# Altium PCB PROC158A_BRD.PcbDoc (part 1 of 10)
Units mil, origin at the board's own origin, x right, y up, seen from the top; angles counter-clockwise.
Board outline 3346.45 x 4921.26 mil, 8 copper layers (Top Layer, GND1, SIG1, PWR1, PWR2, SIG2, GND2, Bottom Layer), stack 54.534 mil thick; 718 components, 459 nets, 2307 pads, 1179 vias.
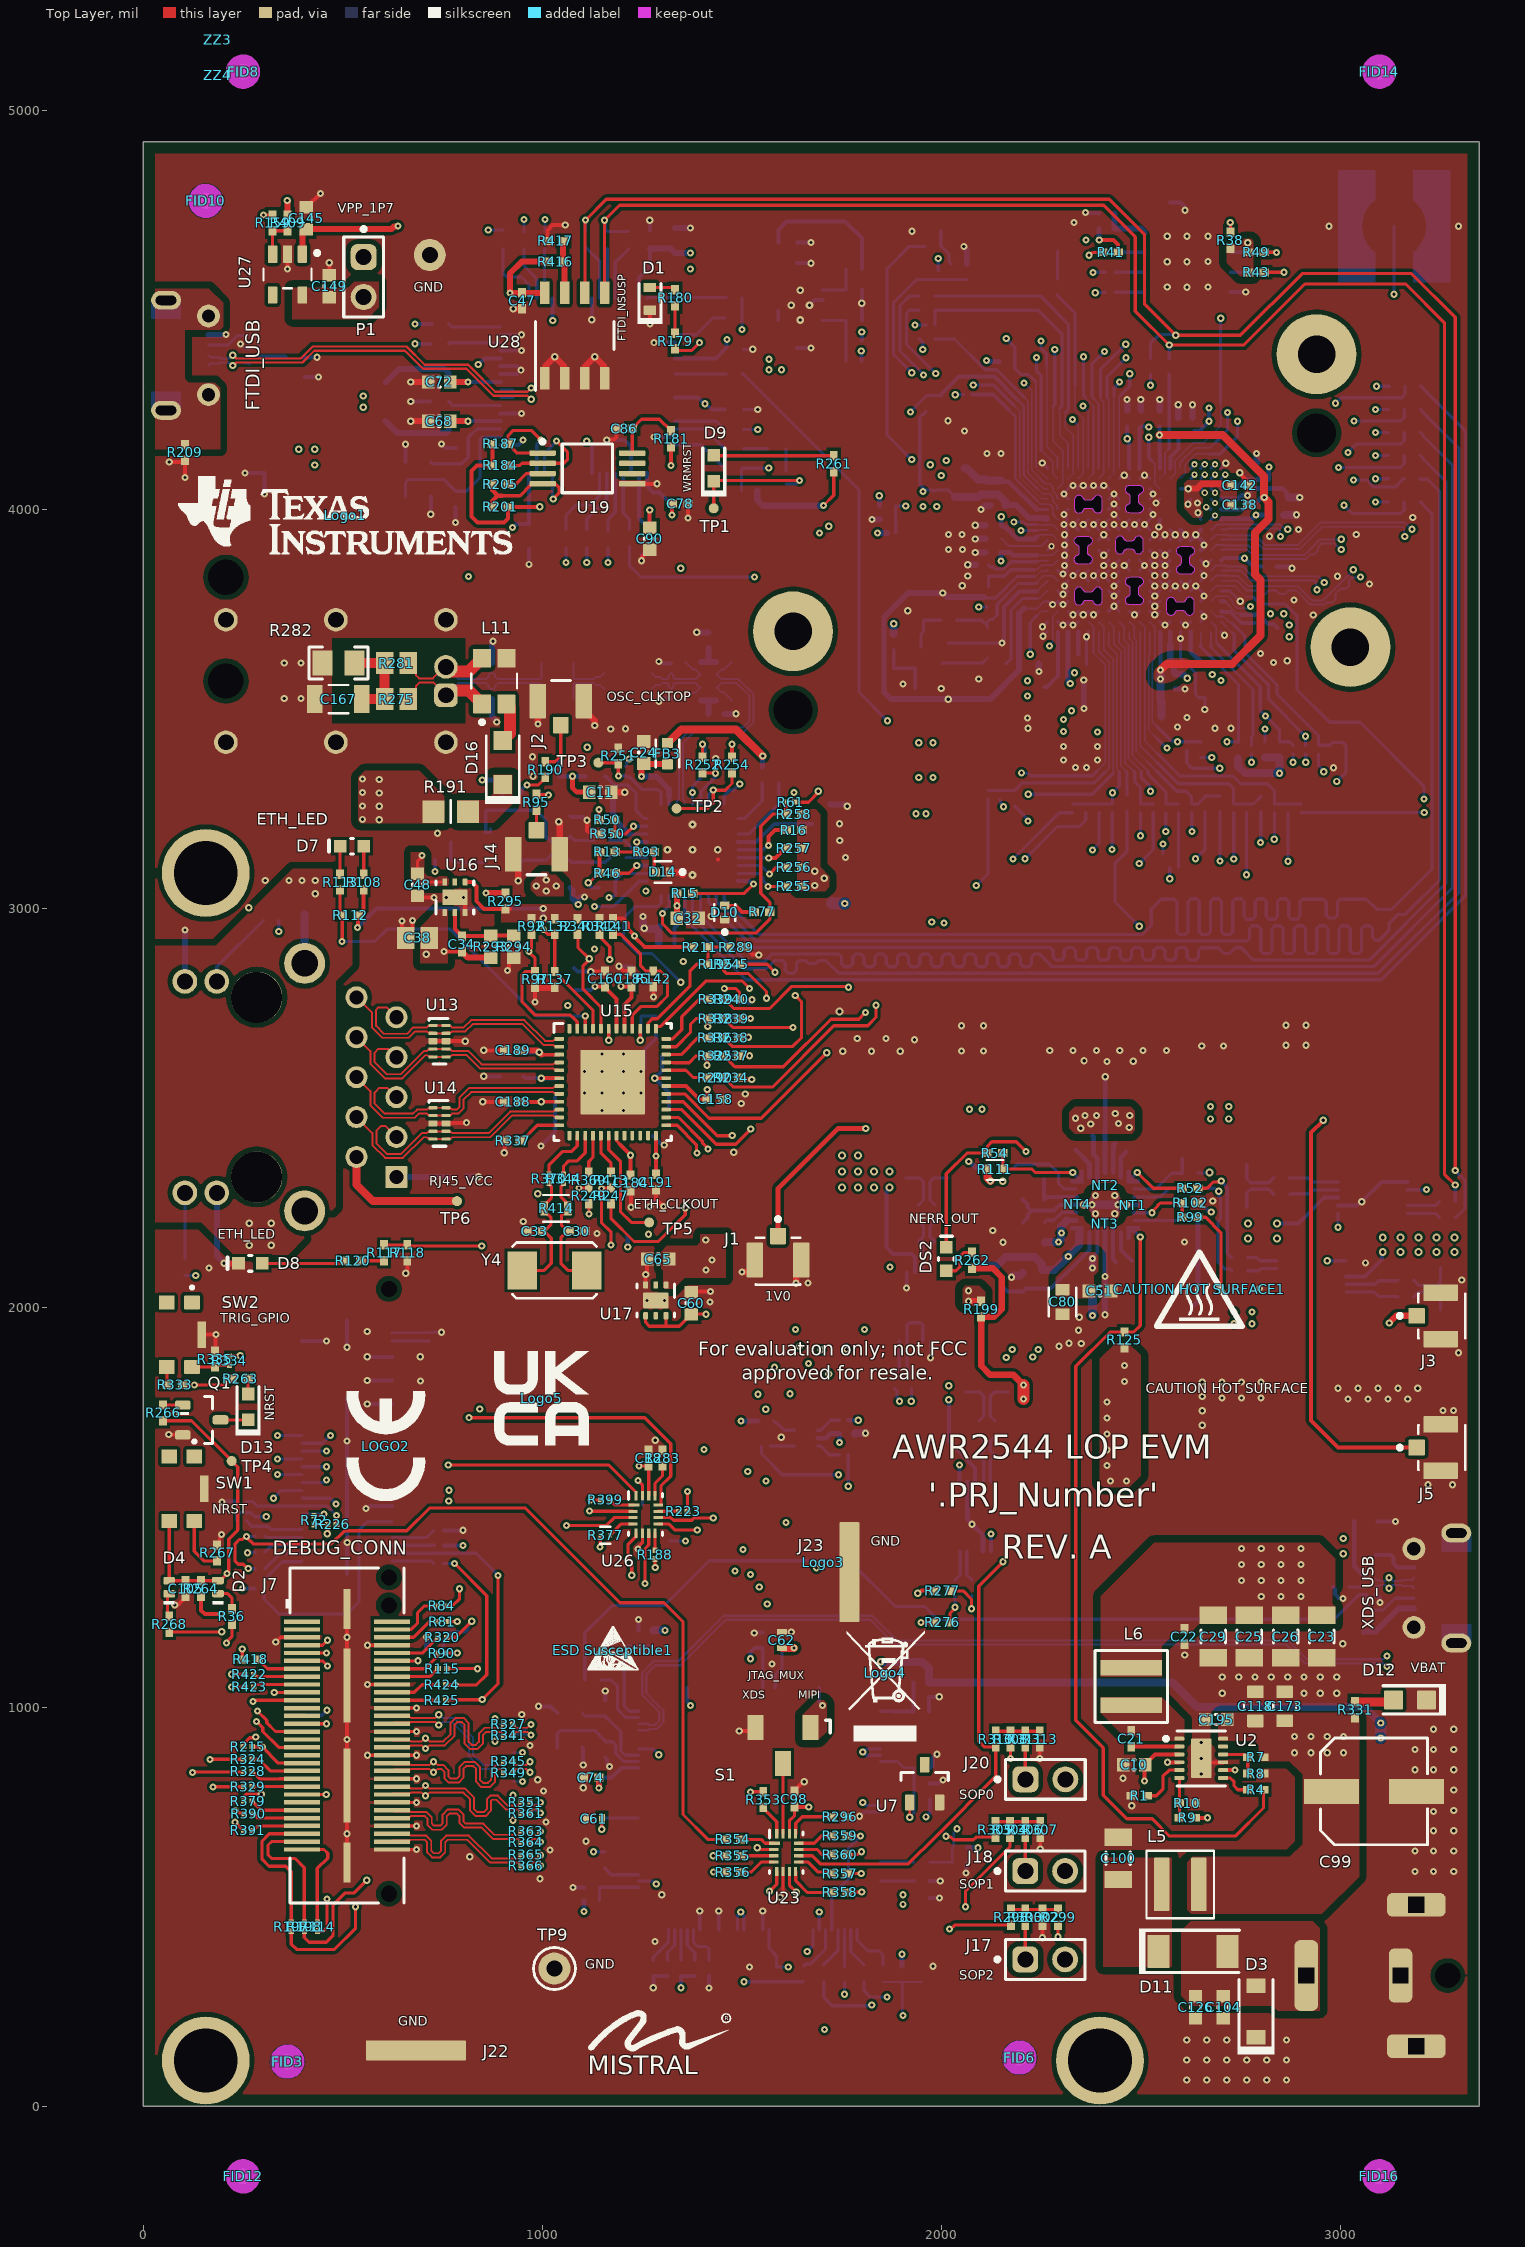
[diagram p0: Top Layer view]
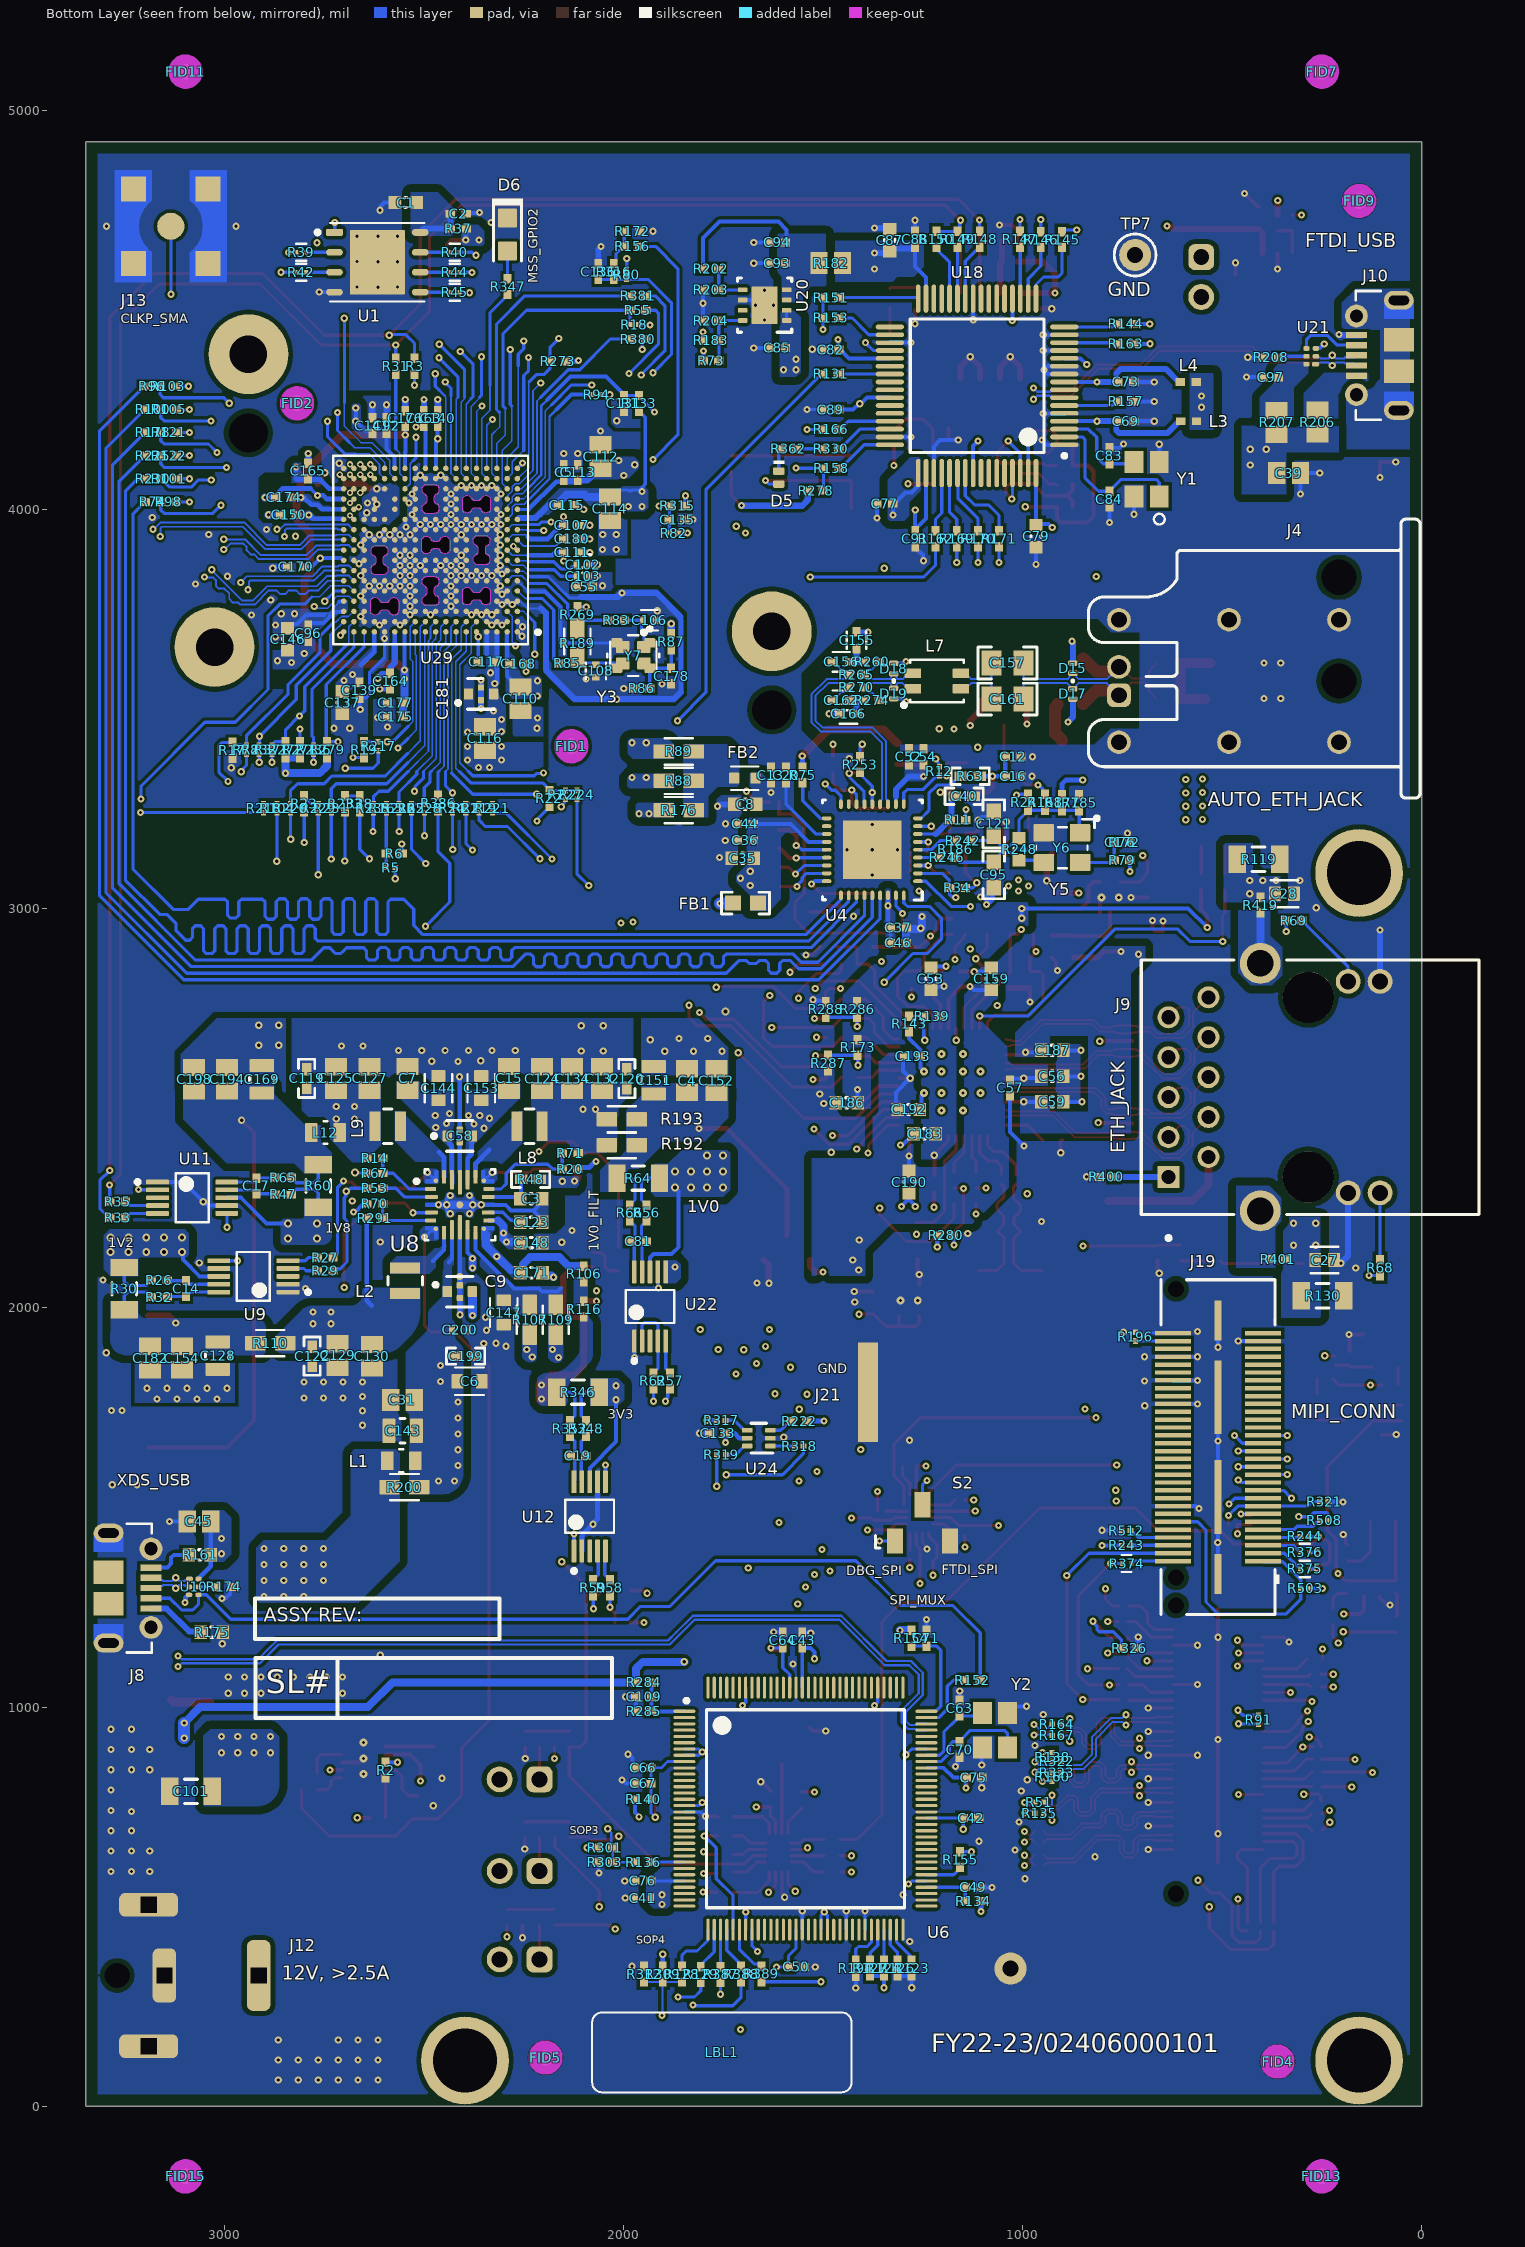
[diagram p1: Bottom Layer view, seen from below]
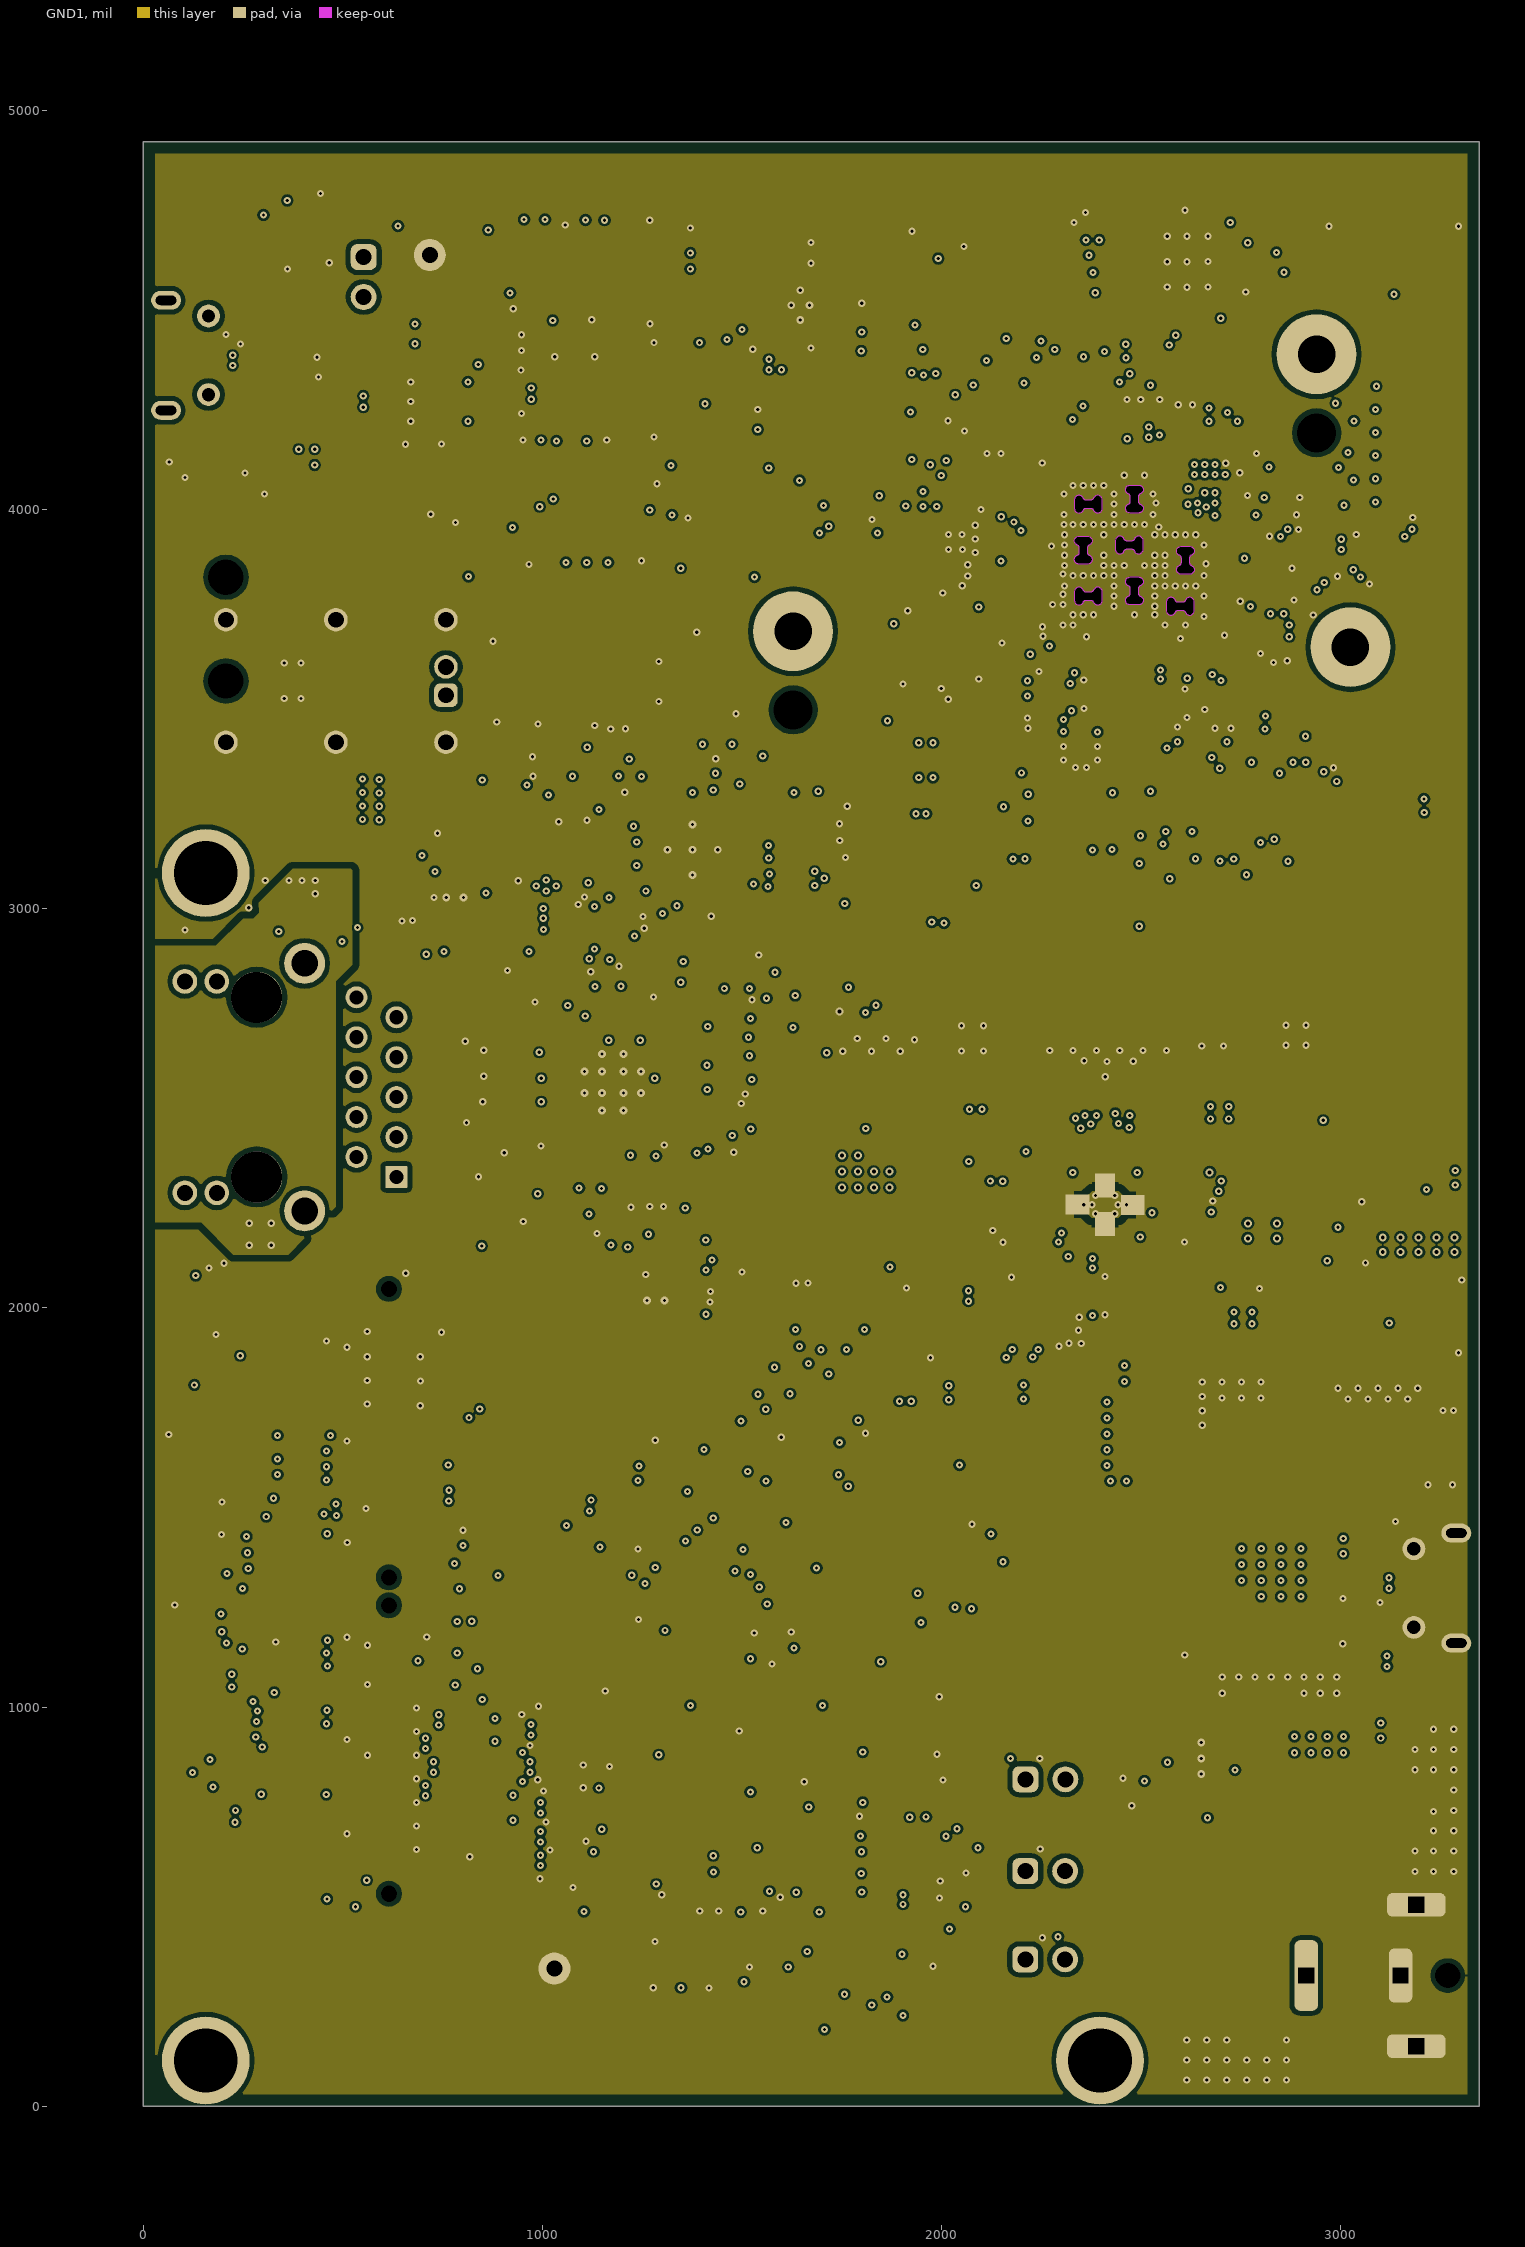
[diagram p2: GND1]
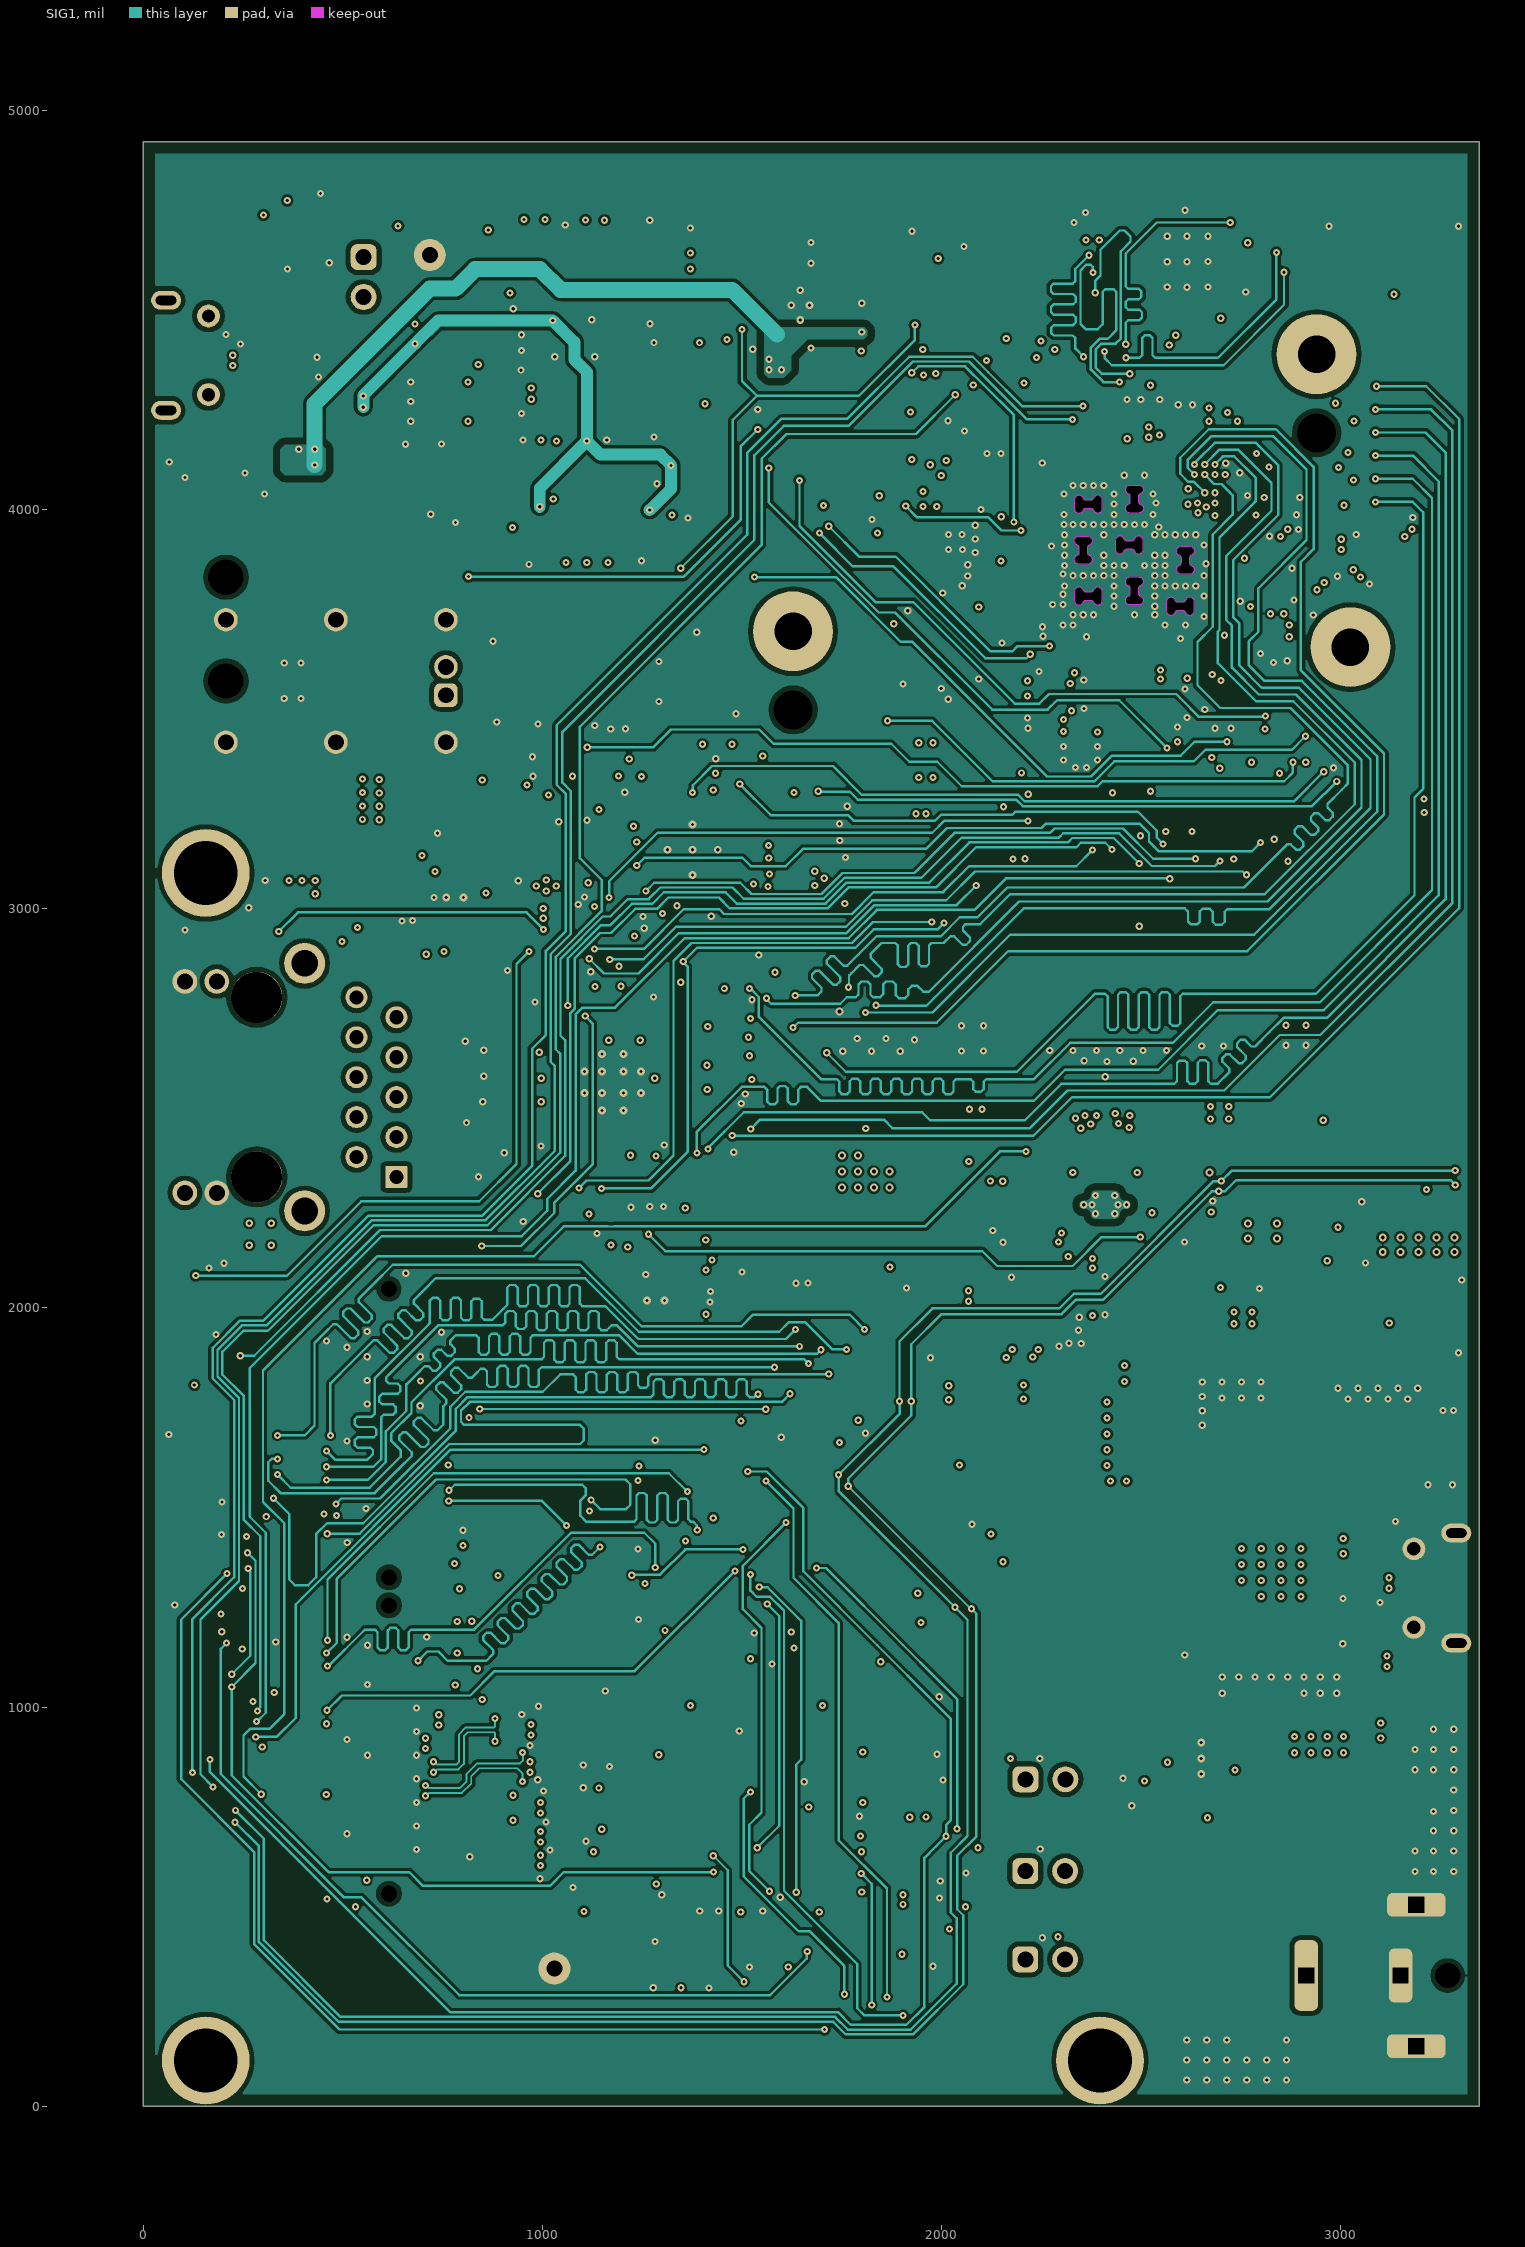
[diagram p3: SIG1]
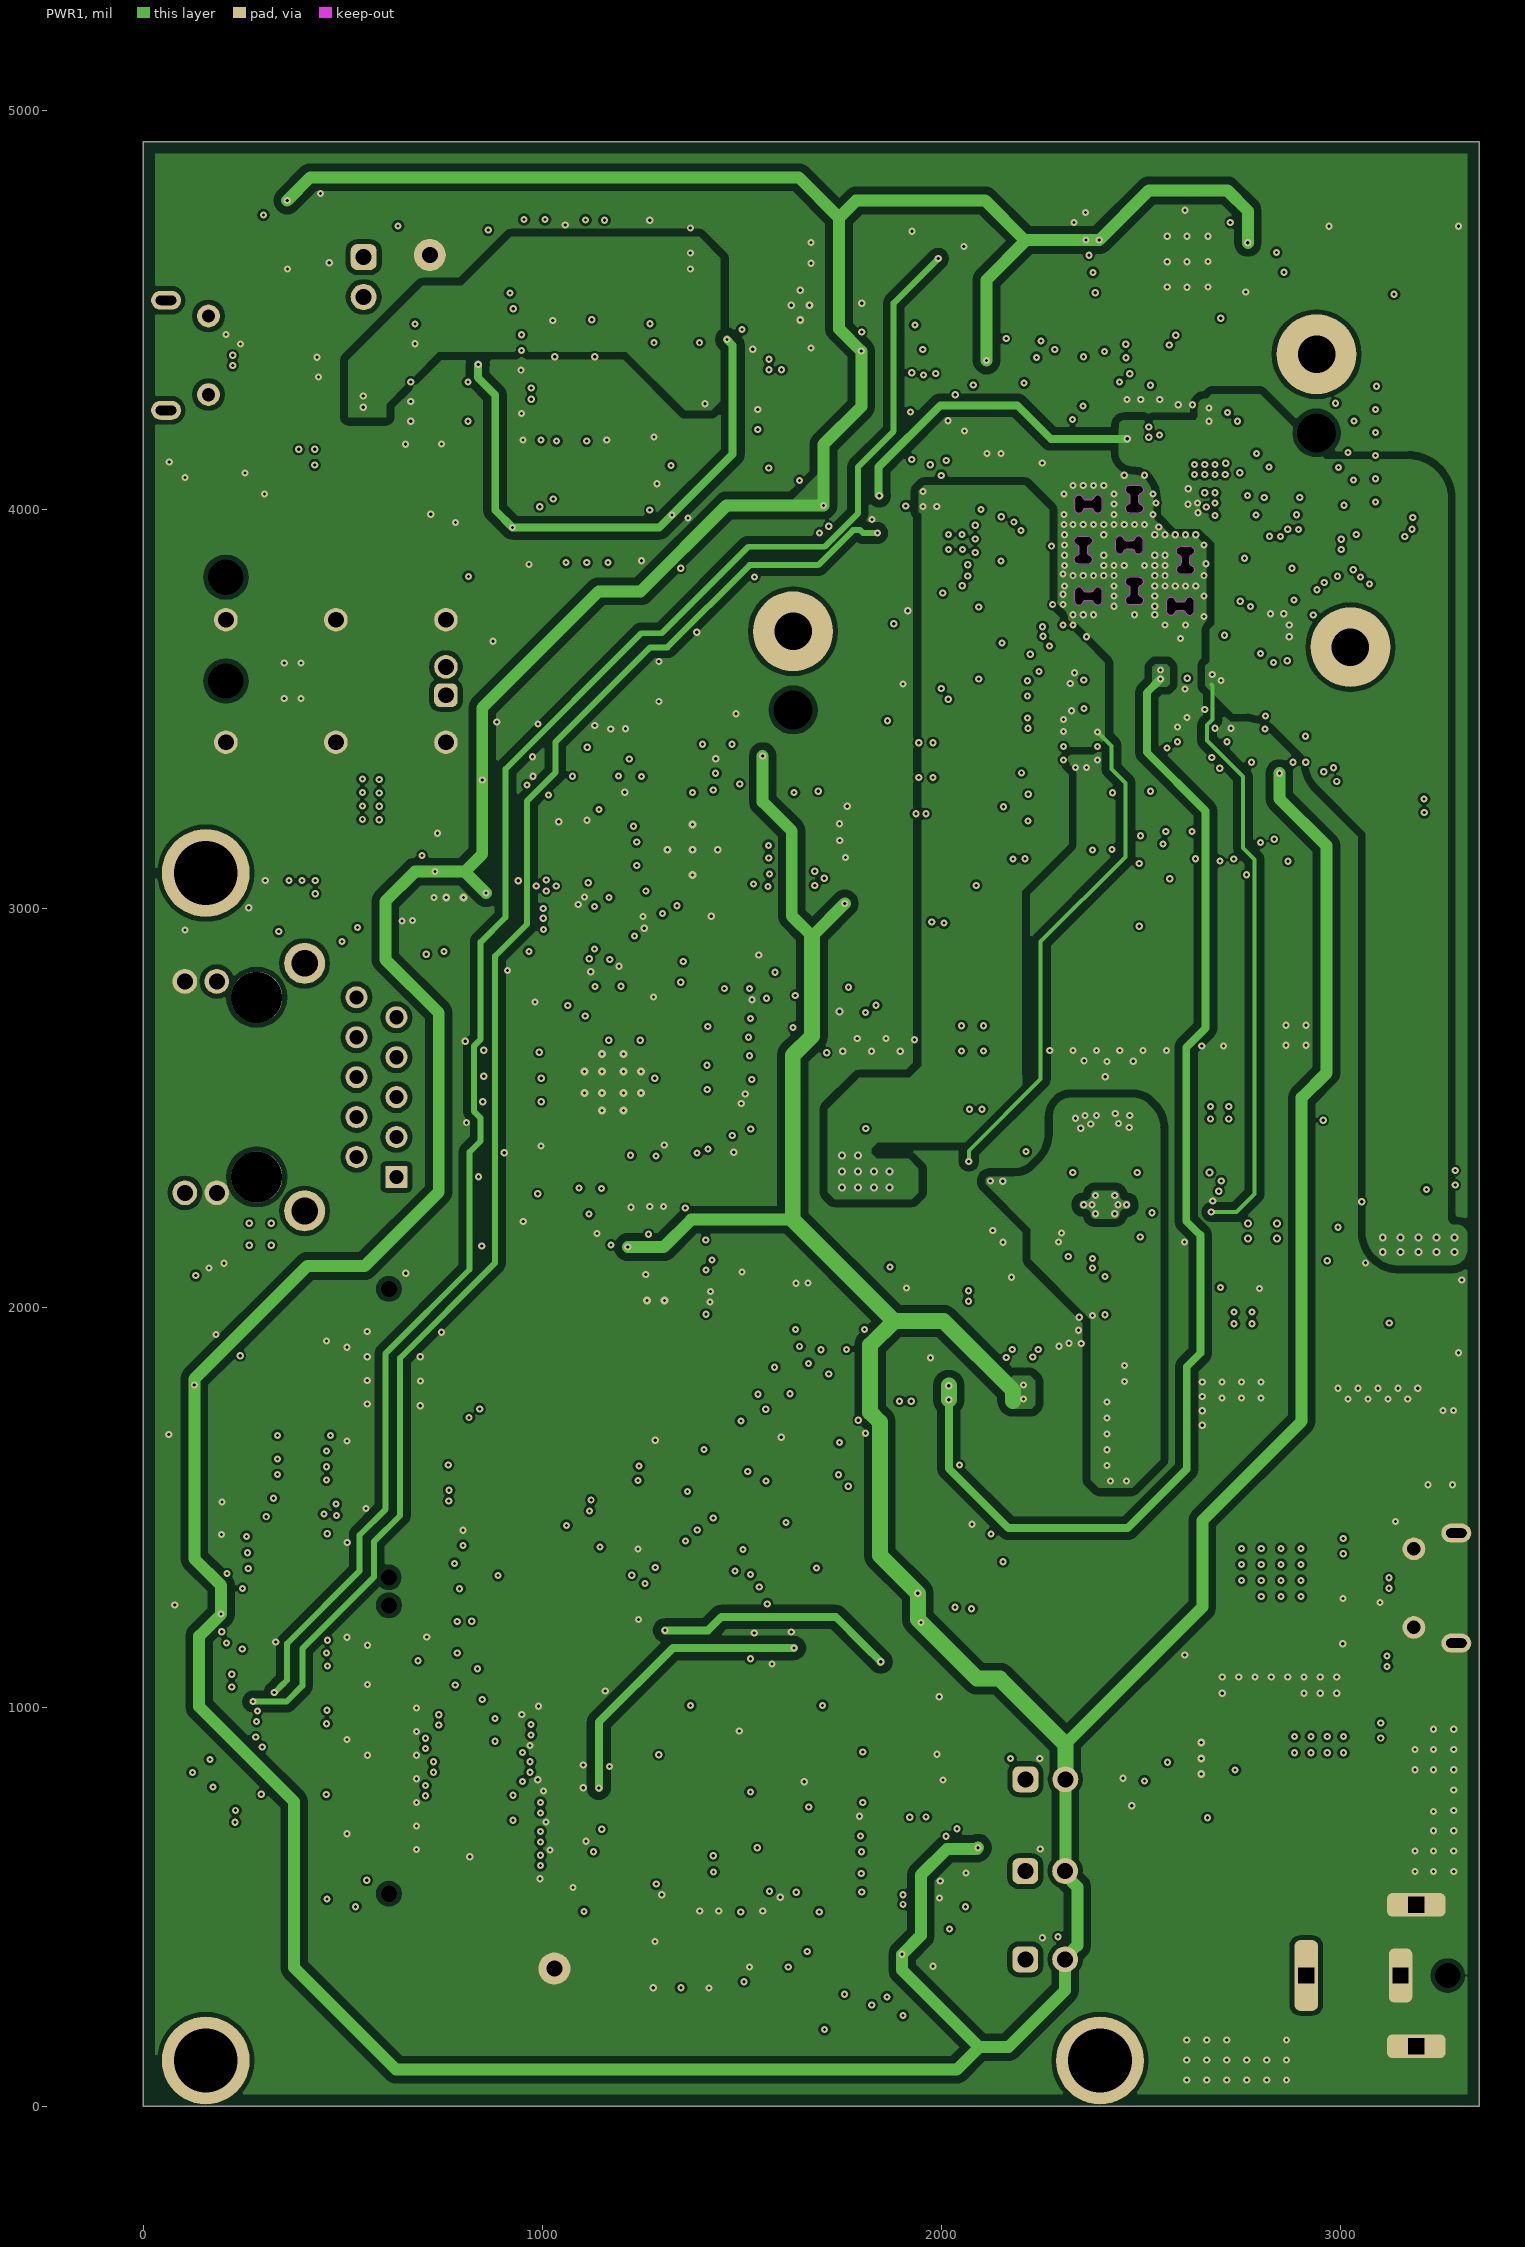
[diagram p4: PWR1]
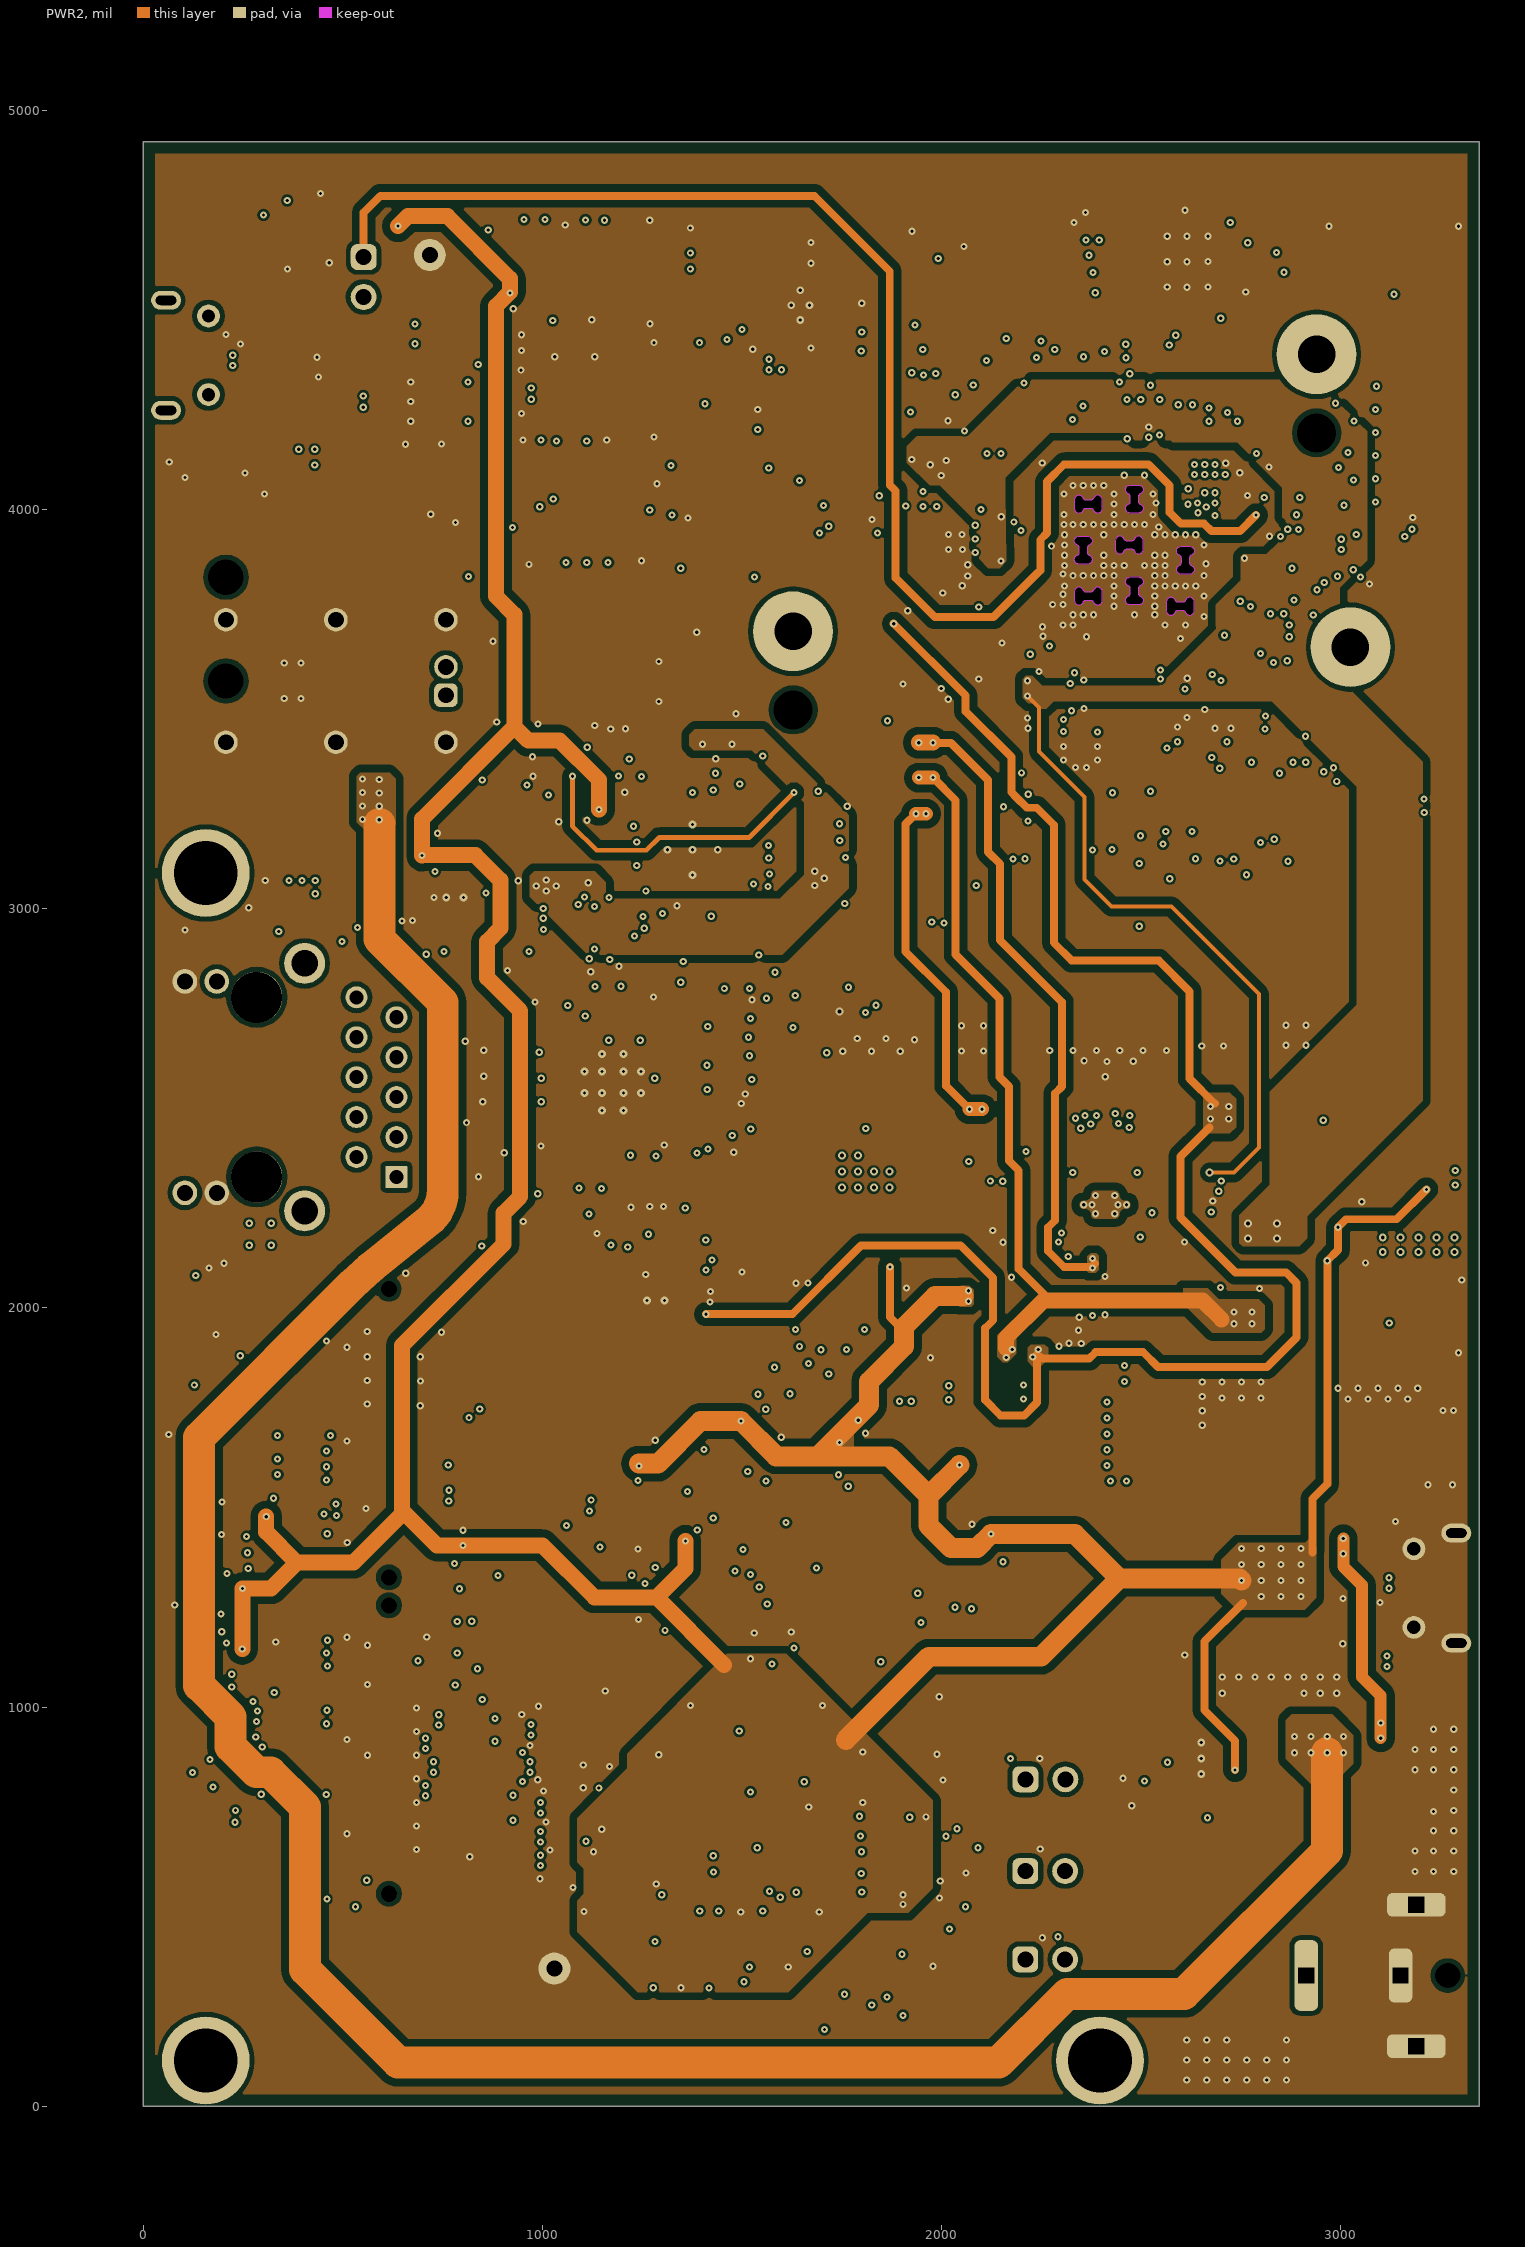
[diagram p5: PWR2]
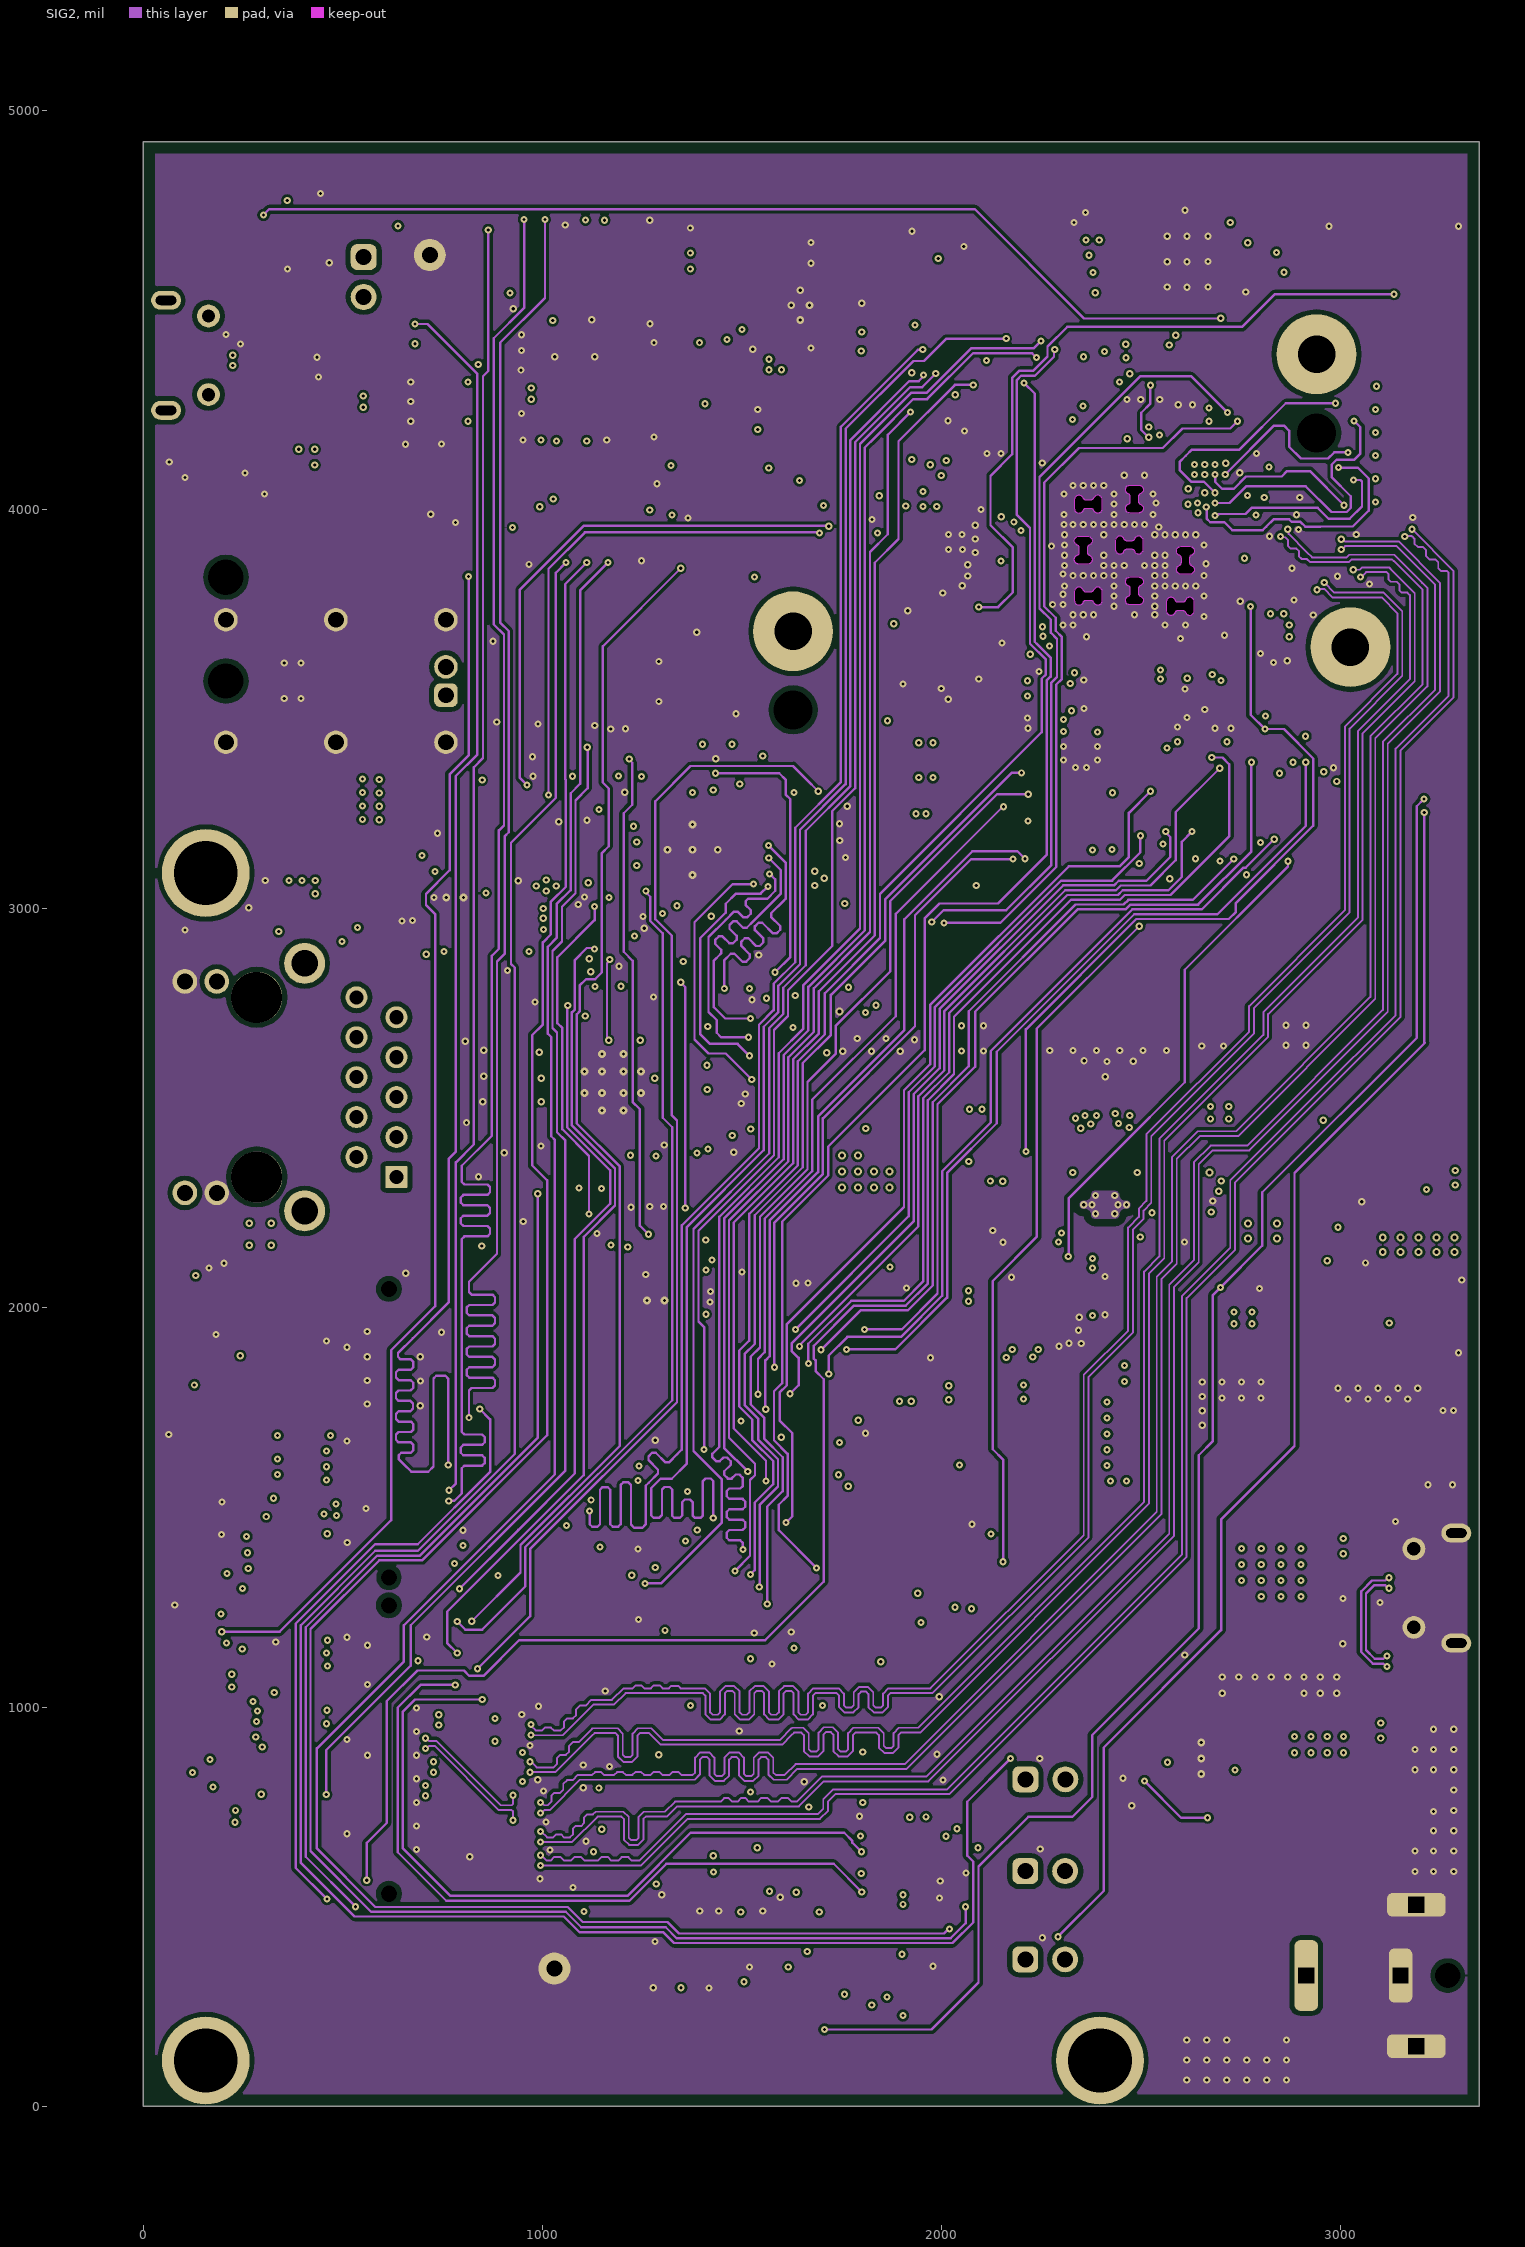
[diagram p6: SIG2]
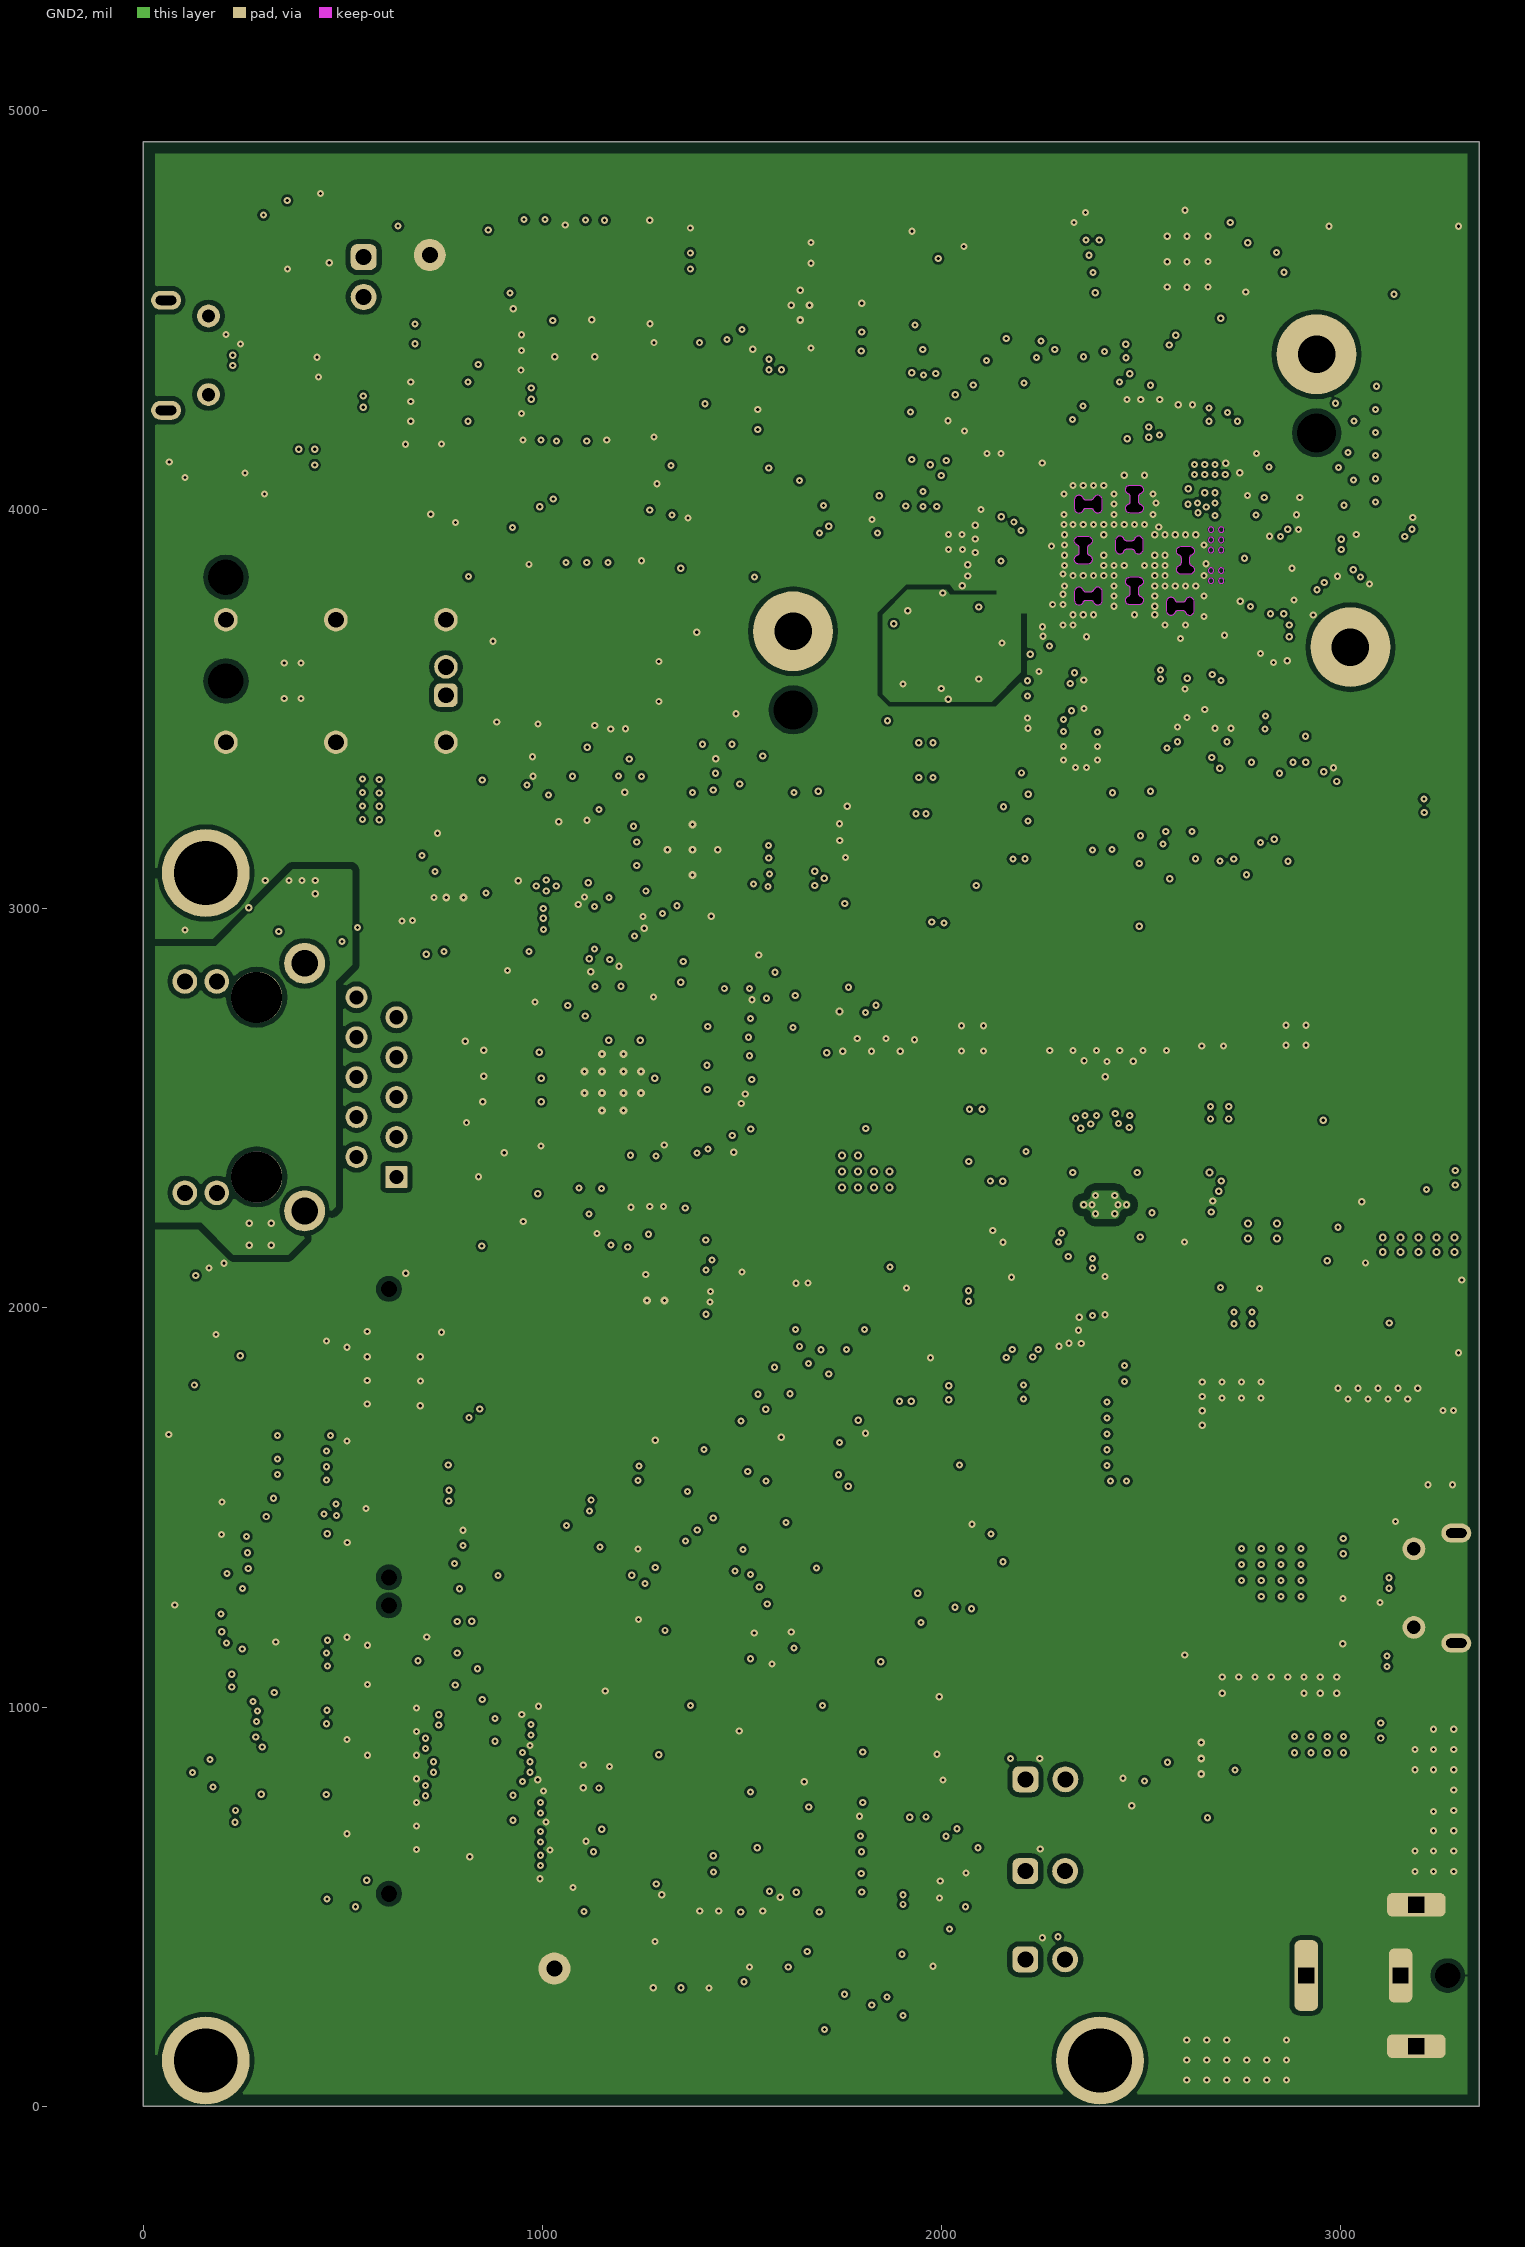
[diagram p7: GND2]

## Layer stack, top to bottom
Top Solder: solder mask 1, Solder Resist, Dk 3.5
Top Layer: signal copper 1.85
Dielectric 1: prepreg 4.396, FR-4 High Tg, Dk 3.54
GND1: signal copper 1.26
Dielectric 2: core 5, FR-4 High Tg, Dk 3.88
SIG1: signal copper 0.689
Dielectric 3: prepreg 10.312, FR-4 High Tg, Dk 3.86
PWR1: signal copper 1.26
Dielectric 4: prepreg 5, FR-4 High Tg, Dk 3.88
PWR2: signal copper 1.26
Dielectric 5: prepreg 10.312, FR-4 High Tg, Dk 3.86
SIG2: signal copper 0.689
Dielectric 6: core 5, FR-4 High Tg, Dk 3.88
GND2: signal copper 1.26
Dielectric 7: prepreg 4.396, FR-4 High Tg, Dk 3.54
Bottom Layer: signal copper 1.85
Bottom Solder: solder mask 1, Solder Resist, Dk 3.5

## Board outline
0,0 3346.45,0 3346.45,4921.25 0,4921.26
cut-out: 2438.45,3892.26 ccw(c2446.8,3900.61) 2446.6,3888.8 ccw(c2446.4,3900.61) 2454.76,3892.26 ccw(c2446.4,3900.61) 2457.38,3896.24 cw(c2464.69,3893.33) 2460.27,3899.84 cw(c2464.69,3893.33) 2464.69,3901.2 2475.36,3901.2 cw(c2475.36,3893.33) 2479.78,3899.84 cw(c2475.36,3893.33) 2482.67,3896.24 ccw(c2493.65,3900.61) 2485.3,3892.26 ccw(c2493.65,3900.61) 2493.45,3888.8 ccw(c2493.25,3900.61) 2501.61,3892.26 ccw(c2493.25,3900.61) 2505.07,3900.61 2505.07,3921.48 ccw(c2493.25,3921.48) 2501.61,3929.83 ccw(c2493.25,3921.48) 2493.45,3933.29 ccw(c2493.65,3921.48) 2485.3,3929.83 ccw(c2493.65,3921.48) 2482.67,3925.85 cw(c2475.36,3928.76) 2479.78,3922.24 cw(c2475.36,3928.76) 2475.36,3920.89 2464.69,3920.89 cw(c2464.69,3928.76) 2460.27,3922.24 cw(c2464.69,3928.76) 2457.38,3925.85 ccw(c2446.41,3921.48) 2454.76,3929.83 ccw(c2446.4,3921.48) 2446.6,3933.29 ccw(c2446.8,3921.48) 2438.45,3929.83 ccw(c2446.8,3921.48) 2434.99,3921.48 2434.99,3900.61 ccw(c2446.8,3900.61) 2435.01,3899.93 ccw(c2446.8,3900.61)
cut-out: 2336.08,3866.67 cw(c2344.44,3875.02) 2332.63,3874.82 cw(c2344.43,3874.63) 2336.08,3882.98 cw(c2344.43,3874.63) 2340.07,3885.6 ccw(c2337.15,3892.91) 2343.67,3888.5 ccw(c2337.15,3892.91) 2345.03,3892.91 2345.03,3903.58 ccw(c2337.15,3903.58) 2343.67,3908 ccw(c2337.15,3903.58) 2340.07,3910.9 cw(c2344.43,3921.87) 2336.08,3913.52 cw(c2344.44,3921.87) 2332.63,3921.67 cw(c2344.43,3921.48) 2336.08,3929.83 cw(c2344.43,3921.48) 2344.44,3933.29 2365.3,3933.29 cw(c2365.3,3921.48) 2373.65,3929.83 cw(c2365.3,3921.48) 2377.11,3921.67 cw(c2365.3,3921.87) 2373.65,3913.52 cw(c2365.3,3921.87) 2369.67,3910.9 ccw(c2372.58,3903.58) 2366.07,3908 ccw(c2372.58,3903.58) 2364.71,3903.58 2364.71,3892.91 ccw(c2372.58,3892.91) 2366.07,3888.5 ccw(c2372.59,3892.91) 2369.67,3885.6 cw(c2365.3,3874.63) 2373.65,3882.98 cw(c2365.3,3874.63) 2377.11,3874.82 cw(c2365.3,3875.02) 2373.65,3866.67 cw(c2365.3,3875.02) 2365.98,3863.23 cw(c2365.3,3875.02) 2365.3,3863.21 2344.44,3863.21 cw(c2344.44,3875.02)
cut-out: 2336.08,3994.62 ccw(c2344.43,4002.97) 2344.24,3991.16 ccw(c2344.04,4002.97) 2352.39,3994.62 ccw(c2344.04,4002.97) 2355.01,3998.6 cw(c2362.33,3995.69) 2357.91,4002.21 cw(c2362.33,3995.69) 2362.33,4003.56 2373,4003.56 cw(c2373,3995.69) 2377.42,4002.21 cw(c2373,3995.69) 2380.31,3998.6 ccw(c2391.28,4002.97) 2382.93,3994.62 ccw(c2391.29,4002.97) 2391.09,3991.16 ccw(c2390.89,4002.97) 2399.24,3994.62 ccw(c2390.89,4002.97) 2402.7,4002.97 2402.7,4023.84 ccw(c2390.89,4023.84) 2399.24,4032.19 ccw(c2390.89,4023.84) 2391.09,4035.65 ccw(c2391.28,4023.84) 2382.93,4032.19 ccw(c2391.29,4023.84) 2380.31,4028.21 cw(c2373,4031.12) 2377.42,4024.61 cw(c2373,4031.12) 2373,4023.25 2362.33,4023.25 cw(c2362.33,4031.12) 2357.91,4024.61 cw(c2362.33,4031.12) 2355.01,4028.21 ccw(c2344.04,4023.84) 2352.39,4032.19 ccw(c2344.04,4023.84) 2344.24,4035.65 ccw(c2344.43,4023.84) 2336.08,4032.19 ccw(c2344.44,4023.84) 2332.62,4023.84 2332.62,4002.97 ccw(c2344.43,4002.97) 2332.64,4002.29 ccw(c2344.43,4002.97)
cut-out: 2464.04,3994.62 cw(c2472.39,4002.97) 2460.58,4002.78 cw(c2472.39,4002.58) 2464.04,4010.93 cw(c2472.39,4002.58) 2468.02,4013.55 ccw(c2465.1,4020.87) 2471.62,4016.45 ccw(c2465.1,4020.87) 2472.98,4020.87 2472.98,4031.54 ccw(c2465.11,4031.54) 2471.62,4035.95 ccw(c2465.11,4031.54) 2468.02,4038.85 cw(c2472.39,4049.82) 2464.04,4041.47 cw(c2472.39,4049.82) 2460.58,4049.63 cw(c2472.39,4049.43) 2464.04,4057.78 cw(c2472.39,4049.43) 2472.39,4061.24 2493.25,4061.24 cw(c2493.25,4049.43) 2501.61,4057.78 cw(c2493.25,4049.43) 2505.06,4049.63 cw(c2493.26,4049.82) 2501.61,4041.47 cw(c2493.25,4049.82) 2497.62,4038.85 ccw(c2500.54,4031.54) 2494.02,4035.95 ccw(c2500.54,4031.54) 2492.66,4031.54 2492.66,4020.87 ccw(c2500.54,4020.87) 2494.02,4016.45 ccw(c2500.54,4020.87) 2497.62,4013.55 cw(c2493.26,4002.58) 2501.61,4010.93 cw(c2493.25,4002.58) 2505.06,4002.78 cw(c2493.26,4002.97) 2501.61,3994.62 cw(c2493.25,4002.97) 2493.94,3991.18 cw(c2493.25,4002.98) 2493.25,3991.16 2472.39,3991.16 cw(c2472.39,4002.97)
cut-out: 2336.08,3764.31 ccw(c2344.43,3772.66) 2344.24,3760.85 ccw(c2344.04,3772.66) 2352.39,3764.31 ccw(c2344.04,3772.66) 2355.01,3768.29 cw(c2362.33,3765.37) 2357.91,3771.89 cw(c2362.33,3765.37) 2362.33,3773.25 2373,3773.25 cw(c2373,3765.38) 2377.42,3771.89 cw(c2373,3765.38) 2380.31,3768.29 ccw(c2391.28,3772.66) 2382.93,3764.31 ccw(c2391.29,3772.66) 2391.09,3760.85 ccw(c2390.89,3772.66) 2399.24,3764.31 ccw(c2390.89,3772.66) 2402.7,3772.66 2402.7,3793.52 ccw(c2390.89,3793.52) 2399.24,3801.88 ccw(c2390.89,3793.52) 2391.09,3805.33 ccw(c2391.28,3793.53) 2382.93,3801.88 ccw(c2391.29,3793.52) 2380.31,3797.89 cw(c2373,3800.81) 2377.42,3794.29 cw(c2373,3800.81) 2373,3792.93 2362.33,3792.93 cw(c2362.33,3800.81) 2357.91,3794.29 cw(c2362.33,3800.81) 2355.01,3797.89 ccw(c2344.04,3793.53) 2352.39,3801.88 ccw(c2344.04,3793.52) 2344.24,3805.33 ccw(c2344.43,3793.53) 2336.08,3801.88 ccw(c2344.44,3793.52) 2332.62,3793.52 2332.62,3772.66 ccw(c2344.43,3772.66) 2332.64,3771.97 ccw(c2344.43,3772.66)
cut-out: 2464.04,3764.31 cw(c2472.39,3772.66) 2460.58,3772.46 cw(c2472.39,3772.26) 2464.04,3780.62 cw(c2472.39,3772.26) 2468.02,3783.24 ccw(c2465.1,3790.55) 2471.62,3786.13 ccw(c2465.1,3790.55) 2472.98,3790.55 2472.98,3801.22 ccw(c2465.11,3801.22) 2471.62,3805.64 ccw(c2465.11,3801.22) 2468.02,3808.54 cw(c2472.39,3819.51) 2464.04,3811.16 cw(c2472.39,3819.51) 2460.58,3819.31 cw(c2472.39,3819.11) 2464.04,3827.47 cw(c2472.39,3819.11) 2472.39,3830.93 2493.25,3830.93 cw(c2493.25,3819.12) 2501.61,3827.47 cw(c2493.25,3819.11) 2505.06,3819.31 cw(c2493.26,3819.51) 2501.61,3811.16 cw(c2493.25,3819.51) 2497.62,3808.54 ccw(c2500.54,3801.22) 2494.02,3805.64 ccw(c2500.54,3801.22) 2492.66,3801.22 2492.66,3790.55 ccw(c2500.54,3790.55) 2494.02,3786.13 ccw(c2500.54,3790.55) 2497.62,3783.24 cw(c2493.26,3772.27) 2501.61,3780.62 cw(c2493.25,3772.26) 2505.06,3772.46 cw(c2493.26,3772.66) 2501.61,3764.31 cw(c2493.25,3772.66) 2493.94,3760.87 cw(c2493.25,3772.66) 2493.25,3760.85 2472.39,3760.85 cw(c2472.39,3772.66)
cut-out: 2591.99,3841.08 cw(c2600.34,3849.43) 2588.53,3849.23 cw(c2600.34,3849.04) 2591.99,3857.39 cw(c2600.34,3849.04) 2595.97,3860.01 ccw(c2593.06,3867.32) 2599.57,3862.9 ccw(c2593.06,3867.32) 2600.93,3867.32 2600.93,3877.99 ccw(c2593.06,3877.99) 2599.57,3882.41 ccw(c2593.06,3877.99) 2595.97,3885.31 cw(c2600.34,3896.28) 2591.99,3887.93 cw(c2600.34,3896.28) 2588.53,3896.08 cw(c2600.34,3895.89) 2591.99,3904.24 cw(c2600.34,3895.89) 2600.34,3907.7 2621.21,3907.7 cw(c2621.21,3895.89) 2629.56,3904.24 cw(c2621.21,3895.89) 2633.02,3896.08 cw(c2621.21,3896.28) 2629.56,3887.93 cw(c2621.21,3896.28) 2625.58,3885.31 ccw(c2628.49,3877.99) 2621.97,3882.41 ccw(c2628.49,3877.99) 2620.62,3877.99 2620.62,3867.32 ccw(c2628.49,3867.32) 2621.97,3862.9 ccw(c2628.49,3867.32) 2625.58,3860.01 cw(c2621.21,3849.04) 2629.56,3857.39 cw(c2621.21,3849.04) 2633.02,3849.23 cw(c2621.21,3849.43) 2629.56,3841.08 cw(c2621.21,3849.43) 2621.89,3837.64 cw(c2621.21,3849.43) 2621.21,3837.62 2600.34,3837.62 cw(c2600.34,3849.43)
cut-out: 2566.4,3738.72 ccw(c2574.75,3747.07) 2574.55,3735.26 ccw(c2574.36,3747.07) 2582.71,3738.72 ccw(c2574.36,3747.07) 2585.33,3742.7 cw(c2592.64,3739.78) 2588.23,3746.3 cw(c2592.64,3739.78) 2592.64,3747.66 2603.31,3747.66 cw(c2603.31,3739.78) 2607.73,3746.3 cw(c2603.31,3739.78) 2610.63,3742.7 ccw(c2621.6,3747.07) 2613.25,3738.72 ccw(c2621.6,3747.07) 2621.4,3735.26 ccw(c2621.21,3747.07) 2629.56,3738.72 ccw(c2621.21,3747.07) 2633.02,3747.07 2633.02,3767.93 ccw(c2621.21,3767.93) 2629.56,3776.29 ccw(c2621.21,3767.93) 2621.4,3779.74 ccw(c2621.6,3767.93) 2613.25,3776.29 ccw(c2621.6,3767.93) 2610.63,3772.3 cw(c2603.31,3775.22) 2607.73,3768.7 cw(c2603.31,3775.22) 2603.31,3767.34 2592.64,3767.34 cw(c2592.64,3775.22) 2588.23,3768.7 cw(c2592.64,3775.22) 2585.33,3772.3 ccw(c2574.36,3767.94) 2582.71,3776.29 ccw(c2574.36,3767.93) 2574.55,3779.74 ccw(c2574.75,3767.93) 2566.4,3776.29 ccw(c2574.75,3767.93) 2562.94,3767.93 2562.94,3747.07 ccw(c2574.75,3747.07) 2562.96,3746.38 ccw(c2574.75,3747.07)

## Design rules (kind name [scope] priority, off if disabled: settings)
AcuteAngle [All] p1: minimum=4.50000000000000E+0001 checktracksonly=TRUE
AssemblyTestPointUsage [All] p1: valid=2
BoardOutlineClearance Outline_BGA [WithinRoom('BGA') or WithinRoom('RouteCNTRL')] p1: gap=0 ignorepadtopadclearanceinfootprint=FALSE
BoardOutlineClearance BoardOutlineClearance_MountingHoles [OnCopper and InComponentClass('Mounting Holes')] p2: gap=39.37 ignorepadtopadclearanceinfootprint=FALSE
BoardOutlineClearance BoardOutlineClearance_Poly [OnCopper and IsPoly] p3: gap=30 ignorepadtopadclearanceinfootprint=FALSE
BoardOutlineClearance [OnCopper and Not InComponentClass('Logo') and not InComponentClass('FiducialMark')and not InComponentClass('RA PARTS') and not InPoly and not InComponent('J8')] p4: gap=80 ignorepadtopadclearanceinfootprint=FALSE except(0: THPad-OutlineEdge Text-OutlineEdge Text-CavityEdge Text-CutoutEdge Text-SplitBarrior Text-SplitContinuation; 19: Fill-OutlineEdge; 30: Arc-OutlineEdge Track-OutlineEdge SMDPad-OutlineEdge Via-OutlineEdge Poly-OutlineEdge Region-OutlineEdge; 78: Via-CutoutEdge)
Clearance DIFF_SMD_PAD_BGA [InAnyDifferentialPair vs WithinRoom('BGA')] p1: gap=8 ignorepadtopadclearanceinfootprint=TRUE except(1: Arc-Text Track-Text SMDPad-Text THPad-Text Via-Text Fill-Text Poly-Text Region-Text Text-Text; 3.4: Track-SMDPad; 3.9: Track-Track; 4.19: Arc-Via; 6: Via-Fill Via-Poly Via-Region; 7: Arc-Arc Arc-Track; 9.5: Arc-Hole Track-Hole; 10: SMDPad-Fill SMDPad-Poly SMDPad-Region Via-Via Via-Hole Fill-Poly Fill-Hole Poly-Hole Region-Hole; 12: Arc-THPad Track-THPad SMDPad-THPad SMDPad-Hole THPad-THPad THPad-Via THPad-Fill THPad-Poly THPad-Region THPad-Hole; 25: Fill-Fill Fill-Region Poly-Poly Poly-Region Region-Region)
Clearance DIFF_100E_EXT_Same [InDifferentialPairClass('DIFF_100E') vs (OnLayer('Top Layer') OR OnLayer('Bottom Layer'))] p2: gap=8 ignorepadtopadclearanceinfootprint=TRUE except(1: Arc-Text Track-Text SMDPad-Text THPad-Text Via-Text Fill-Text Poly-Text Region-Text Text-Text; 3.9: Track-Track; 4.19: Arc-Via; 6: Track-SMDPad Via-Fill Via-Poly Via-Region; 7: Arc-Arc Arc-Track; 9.5: Arc-Hole Track-Hole; 10: SMDPad-Fill SMDPad-Poly SMDPad-Region Via-Via Via-Hole Fill-Poly Fill-Hole Poly-Hole Region-Hole; 12: Arc-THPad Track-THPad SMDPad-THPad SMDPad-Hole THPad-THPad THPad-Via THPad-Fill THPad-Poly THPad-Region THPad-Hole; 25: Fill-Fill Fill-Region Poly-Poly Poly-Region Region-Region)
Clearance DIFF_100E_EXT [InDifferentialPairClass('DIFF_100E') vs (OnLayer('Top Layer') OR OnLayer('Bottom Layer'))] p3: gap=8 ignorepadtopadclearanceinfootprint=TRUE except(1: Arc-Text Track-Text SMDPad-Text THPad-Text Via-Text Fill-Text Poly-Text Region-Text Text-Text; 4: Track-Track; 4.19: Arc-Via; 6: Track-SMDPad Via-Fill Via-Poly Via-Region; 7: Arc-Arc Arc-Track; 9.5: Arc-Hole Track-Hole; 10: Track-Via SMDPad-Fill SMDPad-Poly SMDPad-Region Via-Via Via-Hole Fill-Poly Fill-Hole Poly-Hole Region-Hole; 12: Arc-THPad Track-THPad SMDPad-THPad SMDPad-Hole THPad-THPad THPad-Via THPad-Fill THPad-Poly THPad-Region THPad-Hole; 25: Fill-Fill Fill-Region Poly-Poly Poly-Region Region-Region)
Clearance DIFF_100E_INT_Same [InDifferentialPairClass('DIFF_100E') vs (OnLayer('SIG1') OR OnLayer('SIG2'))] p4: gap=8 ignorepadtopadclearanceinfootprint=TRUE except(1: Arc-Text Track-Text SMDPad-Text THPad-Text Via-Text Fill-Text Poly-Text Region-Text Text-Text; 5: Arc-Via Track-Via; 6: Via-Fill Via-Poly Via-Region; 7.2: Arc-Arc Arc-Track Track-Track; 9.5: Arc-Hole Track-Hole; 10: SMDPad-Via SMDPad-Fill SMDPad-Poly SMDPad-Region Via-Via Via-Hole Fill-Hole Poly-Hole Region-Hole; 12: Arc-THPad Track-THPad SMDPad-THPad SMDPad-Hole THPad-THPad THPad-Via THPad-Fill THPad-Poly THPad-Region THPad-Hole; 25: Fill-Fill Fill-Poly Fill-Region Poly-Poly Poly-Region Region-Region)
Clearance DIFF_100E_INT [(InNetClass('LVDS') or InNetClass('CSI')) vs (OnLayer ('sig1') OR OnLayer('SIG2'))] p5: gap=8 ignorepadtopadclearanceinfootprint=TRUE except(1: Arc-Text Track-Text SMDPad-Text THPad-Text Via-Text Fill-Text Poly-Text Region-Text Text-Text; 5: Arc-Via Track-Via; 6: Via-Fill Via-Poly Via-Region; 9.5: Arc-Hole Track-Hole; 10: Via-Via Via-Hole Fill-Hole Poly-Hole Region-Hole; 12: Arc-THPad Track-THPad SMDPad-THPad SMDPad-Hole THPad-THPad THPad-Via THPad-Fill THPad-Poly THPad-Region THPad-Hole; 14.6: Arc-Arc Arc-Track Track-Track; 25: Fill-Fill Fill-Poly Fill-Region Poly-Poly Poly-Region Region-Region)
Clearance DIFF_90E_EXT_Same [InDifferentialPairClass('DIFF_90E') vs (OnLayer('Top Layer') OR OnLayer('Bottom Layer'))] p6: gap=8 ignorepadtopadclearanceinfootprint=TRUE except(1: Arc-Text Track-Text SMDPad-Text THPad-Text Via-Text Fill-Text Poly-Text Region-Text Text-Text; 4: Track-Track; 4.19: Arc-Via; 5: Track-Via; 6: Track-SMDPad Via-Fill Via-Poly Via-Region; 7: Arc-Arc Arc-Track; 9.5: Arc-Hole Track-Hole; 10: SMDPad-Fill SMDPad-Poly SMDPad-Region Via-Via Via-Hole Fill-Poly Fill-Hole Poly-Hole Region-Hole; 12: Arc-THPad Track-THPad SMDPad-THPad SMDPad-Hole THPad-THPad THPad-Via THPad-Fill THPad-Poly THPad-Region THPad-Hole; 25: Fill-Fill Fill-Region Poly-Poly Poly-Region Region-Region)
Clearance DIFF_90E_EXT [InDifferentialPairClass('DIFF_90E') vs (OnLayer('Top Layer') OR OnLayer('Bottom Layer'))] p7: gap=8 ignorepadtopadclearanceinfootprint=TRUE except(1: Arc-Text Track-Text SMDPad-Text THPad-Text Via-Text Fill-Text Poly-Text Region-Text Text-Text; 4.19: Arc-Via; 5: Track-Via; 6: Track-SMDPad Via-Fill Via-Poly Via-Region; 7: Arc-Arc Arc-Track; 9.5: Arc-Hole Track-Hole; 10: SMDPad-Fill SMDPad-Poly SMDPad-Region Via-Via Via-Hole Fill-Poly Fill-Hole Poly-Hole Region-Hole; 12: Arc-THPad Track-THPad SMDPad-THPad SMDPad-Hole THPad-THPad THPad-Via THPad-Fill THPad-Poly THPad-Region THPad-Hole; 13.4: Track-Track; 25: Fill-Fill Fill-Region Poly-Poly Poly-Region Region-Region)
Clearance Clearance_CNTRL [WithinRoom('RouteCNTRL') vs OnLayer('Bottom Layer')] p8: gap=8 ignorepadtopadclearanceinfootprint=TRUE except(0: Poly-Region; 5.5: Arc-Arc Arc-Track Track-Track; 6: Arc-SMDPad Arc-Via Track-SMDPad Track-Via Via-Poly; 10: Arc-Hole Track-Hole Via-Hole Fill-Hole Poly-Hole Region-Hole; 12: SMDPad-THPad SMDPad-Hole THPad-THPad THPad-Via THPad-Fill THPad-Poly THPad-Region THPad-Hole; 18: Fill-Fill Fill-Poly Fill-Region Poly-Poly Region-Region)
Clearance 0.65MM_BGA [WithinRoom('BGA') vs OnLayer('Bottom Layer')] p9: gap=4 ignorepadtopadclearanceinfootprint=TRUE except(0: Poly-Region Poly-Hole; 3.6: SMDPad-Via; 3.9: Arc-SMDPad Track-SMDPad; 6: Via-Via; 7: Via-Hole; 8: Arc-Hole Track-Poly SMDPad-SMDPad SMDPad-Fill SMDPad-Poly SMDPad-Hole Fill-Hole Region-Hole Text-Hole; 12: Arc-THPad Track-THPad SMDPad-THPad THPad-THPad THPad-Via THPad-Fill THPad-Poly THPad-Region THPad-Hole; 20: Fill-Fill Fill-Poly Fill-Region Poly-Poly Region-Region)
Clearance Clearance_AGND [InNamedPolygon('Top Layer-AGND 1')] p10: gap=10 ignorepadtopadclearanceinfootprint=FALSE except(0: Arc-Hole Track-Hole SMDPad-Hole THPad-Hole Via-Hole Fill-Hole Poly-Hole Region-Hole Text-Hole)
Clearance Clearance_Keepouts [IsKeepOut] p11: gap=1 ignorepadtopadclearanceinfootprint=FALSE
Clearance Clearance_Poly_INT [InPolygon vs OnLayer('PWR1') OR OnLayer('PWR2')] p12: gap=20 ignorepadtopadclearanceinfootprint=TRUE except(5: Arc-Text Track-Text SMDPad-Text THPad-Text Via-Text Fill-Text Poly-Text Region-Text Text-Text; 6: Arc-Via Track-Via SMDPad-Fill SMDPad-Poly SMDPad-Region; 8: Arc-Arc Arc-Track Arc-SMDPad Track-Track Track-SMDPad SMDPad-Via THPad-Via THPad-Fill THPad-Poly THPad-Region Text-Hole; 10: Arc-THPad Arc-Hole Track-THPad Track-Hole Via-Fill Via-Poly Via-Region Via-Hole Fill-Hole Poly-Hole Region-Hole; 12: SMDPad-SMDPad SMDPad-THPad SMDPad-Hole THPad-THPad THPad-Hole Via-Via)
Clearance Clearance_FiducialMark [IsKeepOut and InComponentClass('FiducialMark') vs IsPad and InComponentClass('FiducialMark')] p13: gap=0 ignorepadtopadclearanceinfootprint=FALSE
Clearance Clearance_TOP [All and (not InAnyDifferentialPair) vs OnLayer('Top Layer')] p14: gap=8 ignorepadtopadclearanceinfootprint=TRUE except(0: Poly-Region; 1: Arc-Text Track-Text SMDPad-Text THPad-Text Via-Text Fill-Text Poly-Text Region-Text Text-Text; 5: Arc-Via Track-Via; 6: Via-Fill Via-Poly Via-Region; 7: Arc-Arc Arc-Track Arc-SMDPad Track-Track Track-SMDPad; 9: Arc-Hole Track-Hole; 10: Via-Via Via-Hole Fill-Hole Poly-Hole Region-Hole; 12: SMDPad-THPad SMDPad-Hole THPad-THPad THPad-Via THPad-Fill THPad-Poly THPad-Region THPad-Hole; 18: Fill-Fill Fill-Poly Fill-Region Poly-Poly Region-Region)
Clearance Clearance_U8 [WithinRoom('U8_') or WithinRoom('U6_') vs OnLayer('Bottom Layer')] p15: gap=8 ignorepadtopadclearanceinfootprint=TRUE except(1: Arc-Text Track-Text SMDPad-Text THPad-Text Via-Text Fill-Text Poly-Text Region-Text Text-Text; 4: Arc-Hole Track-Track Track-Hole SMDPad-Hole THPad-Hole Via-Hole Fill-Hole Poly-Hole Region-Hole Text-Hole; 5: Arc-Via Track-Via; 6: SMDPad-Via THPad-Via Via-Fill Via-Poly Via-Region; 7: Arc-Arc Arc-Track Arc-SMDPad Track-SMDPad; 10: Via-Via; 12: SMDPad-THPad THPad-THPad THPad-Fill THPad-Poly THPad-Region; 18: Fill-Fill Fill-Poly Fill-Region Poly-Poly Poly-Region Region-Region)
Clearance 2W_50E_INT [InNetClass('RGMII_TX_RX') AND (OnLayer('SIG1') OR OnLayer('SIG2'))] p16: gap=8 ignorepadtopadclearanceinfootprint=TRUE except(1: Arc-Text Track-Text SMDPad-Text THPad-Text Via-Text Fill-Text Poly-Text Region-Text Text-Text; 5: Arc-Via Track-Via; 5.5: Arc-Arc; 6: Via-Fill Via-Poly Via-Region; 9.5: Arc-Hole Track-Hole; 10: Arc-THPad Track-THPad SMDPad-Fill SMDPad-Poly SMDPad-Region Via-Hole Fill-Poly Fill-Hole Poly-Hole Region-Hole; 11: Arc-Track Track-Track; 12: SMDPad-THPad SMDPad-Hole THPad-THPad THPad-Via THPad-Fill THPad-Poly THPad-Region THPad-Hole; 18: Via-Via; 25: Fill-Fill Fill-Region Poly-Poly Poly-Region Region-Region)
Clearance DIFF_90E_INT [InDifferentialPairClass('DIFF_90E') vs OnLayer('SIG1')] p17: gap=8 ignorepadtopadclearanceinfootprint=TRUE except(1: Arc-Text Track-Text SMDPad-Text THPad-Text Via-Text Fill-Text Poly-Text Region-Text Text-Text; 5: Arc-Via Track-Via; 6: Via-Fill Via-Poly Via-Region; 9.5: Arc-Hole Track-Hole; 10: SMDPad-Fill SMDPad-Poly SMDPad-Region Via-Via Via-Hole Fill-Poly Fill-Hole Poly-Hole Region-Hole; 12: Arc-THPad Track-THPad SMDPad-THPad SMDPad-Hole THPad-THPad THPad-Via THPad-Fill THPad-Poly THPad-Region THPad-Hole; 15: Arc-Arc Arc-Track Track-Track; 25: Fill-Fill Fill-Region Poly-Poly Poly-Region Region-Region)
Clearance Clearance_SOLD [All and (not InAnyDifferentialPair) vs OnLayer('Bottom Layer')] p18: gap=8 ignorepadtopadclearanceinfootprint=TRUE except(1: Arc-Text Track-Text SMDPad-Text THPad-Text Via-Text Fill-Text Poly-Text Region-Text Text-Text; 5: Arc-Via Track-Via; 6: Via-Fill Via-Poly Via-Region; 7: Arc-Arc Arc-Track Arc-SMDPad Track-SMDPad; 8.3: Track-Track; 9: Arc-Hole Track-Hole; 10: Via-Via Via-Hole Fill-Hole Poly-Hole Region-Hole; 12: SMDPad-THPad SMDPad-Hole THPad-THPad THPad-Via THPad-Fill THPad-Poly THPad-Region THPad-Hole; 18: Fill-Fill Fill-Poly Fill-Region Poly-Region Region-Region; 20: Poly-Poly)
Clearance Clearance_Poly_EXT [(InNetClass('PWR') AND OnLayer('Top Layer') AND ('Bottom Layer'))] p19: gap=12 ignorepadtopadclearanceinfootprint=TRUE except(1: Arc-Text Track-Text SMDPad-Text THPad-Text Via-Text Fill-Text Poly-Text Region-Text Text-Text Text-Hole; 6: Via-Fill Via-Poly Via-Region; 8: Arc-Arc Arc-Track Arc-SMDPad Track-Track Track-SMDPad SMDPad-SMDPad SMDPad-Via; 10: Arc-Via Arc-Hole Track-Via Track-Hole Via-Hole Fill-Hole Poly-Hole Region-Hole; 18: Via-Via Fill-Fill Fill-Poly Fill-Region Poly-Poly Poly-Region Region-Region)
Clearance [All] p20: gap=8 ignorepadtopadclearanceinfootprint=TRUE except(0: Poly-Region; 6: Arc-Arc Arc-Track Arc-Via Track-Track Track-Via Via-Fill Via-Poly Via-Region; 10: Arc-Hole Track-Hole Via-Hole Fill-Hole Poly-Hole Region-Hole; 12: SMDPad-THPad SMDPad-Hole THPad-THPad THPad-Via THPad-Fill THPad-Poly THPad-Region THPad-Hole; 18: Fill-Fill Fill-Poly Fill-Region Poly-Poly Region-Region)
ComponentClearance TriPAD [InComponent('R138')or InComponent('R322')or InComponent('R323') or InComponent('R160')] p1: gap=0 collisioncheckmode=3 verticalgap=0 showdistances=FALSE
ComponentClearance ComponentClearance_MountingHoles_FiducialMarks [InComponentClass('Mounting Holes') vs InComponentClass('FiducialMark')] p2: gap=50 collisioncheckmode=3 verticalgap=10 showdistances=FALSE
ComponentClearance ComponentClearance_Shunt [InComponentClass('Header') vs InComponentClass('Shunt')] p3: gap=0 collisioncheckmode=3 verticalgap=0 showdistances=FALSE
ComponentClearance ComponentClearance_Logo [InComponentClass('Logo')] p4: gap=10 collisioncheckmode=3 verticalgap=10 showdistances=FALSE
ComponentClearance ComponentClearance_ScrewToNut [(HasFootprint('NY PMS 440 0025 PH')) vs (HasFootprint('Keystone_1902C'))] p5: gap=5 collisioncheckmode=3 verticalgap=10 showdistances=FALSE
ComponentClearance ComponentClearance_MountingHoles [InComponentClass('Mounting Holes')] p6: gap=250 collisioncheckmode=3 verticalgap=100000 showdistances=FALSE
ComponentClearance ComponentClearance_SmallPassives [HasFootprint('0201*') or  HasFootprint('0508') or HasFootprint('0603*') or HasFootprint('0612') or HasFootprint('0805*') or HasFootprint('0815*') or HasFootprint('0830*') or HasFootprint('1206*') or HasFootprint('1210*') or HasFootprint('1808*') or HasFootprint('1812*') or HasFootprint('1825*') or HasFootprint('2010*') or HasFootprint('2220*') or HasFootprint('2225*') or HasFootprint('2512*') or HasFootprint('2728*') or HasFootprint('3518*') vs HasFootprint('0201*') or HasFootprint('0508') or HasFootprint('0603*') or HasFootprint('0612') or HasFootprint('0805*') or HasFootprint('0815*') or HasFootprint('0830*') or HasFootprint('1206*') or HasFootprint('1210*') or HasFootprint('1808*') or HasFootprint('1812*') or HasFootprint('1825*') or HasFootprint('2010*') or HasFootprint('2220*') or HasFootprint('2225*') or HasFootprint('2512*') or HasFootprint('2728*') or HasFootprint('3518*')] p7: gap=5 collisioncheckmode=3 verticalgap=5 showdistances=FALSE
ComponentClearance ComponentClearance_THtoSMT [IsThruComponent vs IsSMTComponent] p8: gap=10 collisioncheckmode=3 verticalgap=10 showdistances=FALSE
ComponentClearance ComponentClearance_THtoTH [IsThruComponent vs IsThruComponent] p9: gap=20 collisioncheckmode=3 verticalgap=10 showdistances=FALSE
ComponentClearance [All] p10: gap=0 collisioncheckmode=3 verticalgap=0 showdistances=FALSE
ComponentClearance "TRIPAD COMPONENTS" [not InComponentClass('TRIPAD RESISTORS')] p11: gap=0 collisioncheckmode=3 verticalgap=0 showdistances=FALSE
DiffPairsRouting DiffPairsRouting_100E [InDifferentialPairClass('DIFF_100E')] p1: maxlimit=7.2 minlimit=1 mostfreqgap=7.2 toplayer_mingap=5.4 toplayer_maxgap=5.4 toplayer_prefgap=5.4 toplayer_minwidth=4.8 toplayer_maxwidth=4.8 toplayer_prefwidth=4.8 midlayer2_maxgap=1 midlayer2_prefgap=1 midlayer2_minwidth=1 midlayer2_maxwidth=1 midlayer2_prefwidth=1 midlayer3_maxgap=1 midlayer3_prefgap=1 midlayer3_minwidth=1 midlayer3_maxwidth=1 midlayer3_prefwidth=1 midlayer5_maxgap=1 midlayer5_prefgap=1 midlayer5_minwidth=1 midlayer5_maxwidth=1 midlayer5_prefwidth=1 midlayer6_mingap=7.2 midlayer6_minwidth=4.8 midlayer6_maxwidth=4.8 midlayer6_prefwidth=4.8 midlayer7_mingap=7.2 midlayer7_minwidth=4.8 midlayer7_maxwidth=4.8 midlayer7_prefwidth=4.8 midlayer8_maxgap=1 midlayer8_prefgap=1 midlayer8_minwidth=1 midlayer8_maxwidth=1 midlayer8_prefwidth=1 bottomlayer_mingap=5.4 bottomlayer_maxgap=5.4 bottomlayer_prefgap=5.4 bottomlayer_minwidth=4.8 bottomlayer_maxwidth=4.8 bottomlayer_prefwidth=4.8 substack1={9319A519-0D26-40B3-8AF8-C4998BECF1C7} toplayer_{9319a519-0d26-40b3-8af8-c4998becf1c7}_mingap=10 toplayer_{9319a519-0d26-40b3-8af8-c4998becf1c7}_maxgap=10 toplayer_{9319a519-0d26-40b3-8af8-c4998becf1c7}_prefgap=10 toplayer_{9319a519-0d26-40b3-8af8-c4998becf1c7}_minwidth=15 toplayer_{9319a519-0d26-40b3-8af8-c4998becf1c7}_maxwidth=15 toplayer_{9319a519-0d26-40b3-8af8-c4998becf1c7}_prefwidth=15 midlayer2_{9319a519-0d26-40b3-8af8-c4998becf1c7}_mingap=10 midlayer2_{9319a519-0d26-40b3-8af8-c4998becf1c7}_maxgap=10 midlayer2_{9319a519-0d26-40b3-8af8-c4998becf1c7}_prefgap=10 midlayer2_{9319a519-0d26-40b3-8af8-c4998becf1c7}_minwidth=15 midlayer2_{9319a519-0d26-40b3-8af8-c4998becf1c7}_maxwidth=15 midlayer2_{9319a519-0d26-40b3-8af8-c4998becf1c7}_prefwidth=15 midlayer3_{9319a519-0d26-40b3-8af8-c4998becf1c7}_mingap=10 midlayer3_{9319a519-0d26-40b3-8af8-c4998becf1c7}_maxgap=10 midlayer3_{9319a519-0d26-40b3-8af8-c4998becf1c7}_prefgap=10 midlayer3_{9319a519-0d26-40b3-8af8-c4998becf1c7}_minwidth=15 midlayer3_{9319a519-0d26-40b3-8af8-c4998becf1c7}_maxwidth=15 midlayer3_{9319a519-0d26-40b3-8af8-c4998becf1c7}_prefwidth=15 midlayer5_{9319a519-0d26-40b3-8af8-c4998becf1c7}_mingap=10 midlayer5_{9319a519-0d26-40b3-8af8-c4998becf1c7}_maxgap=10 midlayer5_{9319a519-0d26-40b3-8af8-c4998becf1c7}_prefgap=10 midlayer5_{9319a519-0d26-40b3-8af8-c4998becf1c7}_minwidth=15 midlayer5_{9319a519-0d26-40b3-8af8-c4998becf1c7}_maxwidth=15 midlayer5_{9319a519-0d26-40b3-8af8-c4998becf1c7}_prefwidth=15 midlayer6_{9319a519-0d26-40b3-8af8-c4998becf1c7}_mingap=10 midlayer6_{9319a519-0d26-40b3-8af8-c4998becf1c7}_maxgap=10 midlayer6_{9319a519-0d26-40b3-8af8-c4998becf1c7}_prefgap=10 midlayer6_{9319a519-0d26-40b3-8af8-c4998becf1c7}_minwidth=15 midlayer6_{9319a519-0d26-40b3-8af8-c4998becf1c7}_maxwidth=15 midlayer6_{9319a519-0d26-40b3-8af8-c4998becf1c7}_prefwidth=15 midlayer7_{9319a519-0d26-40b3-8af8-c4998becf1c7}_mingap=10 midlayer7_{9319a519-0d26-40b3-8af8-c4998becf1c7}_maxgap=10 midlayer7_{9319a519-0d26-40b3-8af8-c4998becf1c7}_prefgap=10 midlayer7_{9319a519-0d26-40b3-8af8-c4998becf1c7}_minwidth=15 midlayer7_{9319a519-0d26-40b3-8af8-c4998becf1c7}_maxwidth=15 midlayer7_{9319a519-0d26-40b3-8af8-c4998becf1c7}_prefwidth=15 midlayer8_{9319a519-0d26-40b3-8af8-c4998becf1c7}_mingap=10 midlayer8_{9319a519-0d26-40b3-8af8-c4998becf1c7}_maxgap=10 midlayer8_{9319a519-0d26-40b3-8af8-c4998becf1c7}_prefgap=10 midlayer8_{9319a519-0d26-40b3-8af8-c4998becf1c7}_minwidth=15 midlayer8_{9319a519-0d26-40b3-8af8-c4998becf1c7}_maxwidth=15 midlayer8_{9319a519-0d26-40b3-8af8-c4998becf1c7}_prefwidth=15 bottomlayer_{9319a519-0d26-40b3-8af8-c4998becf1c7}_mingap=10 bottomlayer_{9319a519-0d26-40b3-8af8-c4998becf1c7}_maxgap=10 bottomlayer_{9319a519-0d26-40b3-8af8-c4998becf1c7}_prefgap=10 bottomlayer_{9319a519-0d26-40b3-8af8-c4998becf1c7}_minwidth=15 bottomlayer_{9319a519-0d26-40b3-8af8-c4998becf1c7}_maxwidth=15 bottomlayer_{9319a519-0d26-40b3-8af8-c4998becf1c7}_prefwidth=15 maxuncoupledlength=520
DiffPairsRouting DiffPairsRouting_90E [InDifferentialPairClass('DIFF_90E')] p2: maxlimit=6.2 minlimit=1 mostfreqgap=6.2 toplayer_mingap=4.55 toplayer_maxgap=4.55 toplayer_prefgap=4.55 toplayer_minwidth=5.65 toplayer_maxwidth=5.65 toplayer_prefwidth=5.65 midlayer2_maxgap=1 midlayer2_prefgap=1 midlayer2_minwidth=1 midlayer2_maxwidth=1 midlayer2_prefwidth=1 midlayer3_maxgap=1 midlayer3_prefgap=1 midlayer3_minwidth=1 midlayer3_maxwidth=1 midlayer3_prefwidth=1 midlayer5_maxgap=1 midlayer5_prefgap=1 midlayer5_minwidth=1 midlayer5_maxwidth=1 midlayer5_prefwidth=1 midlayer6_mingap=6.2 midlayer6_minwidth=5.8 midlayer6_maxwidth=5.8 midlayer6_prefwidth=5.8 midlayer7_mingap=6.2 midlayer7_minwidth=5.8 midlayer7_maxwidth=5.8 midlayer7_prefwidth=5.8 midlayer8_maxgap=1 midlayer8_prefgap=1 midlayer8_minwidth=1 midlayer8_maxwidth=1 midlayer8_prefwidth=1 bottomlayer_mingap=4.55 bottomlayer_maxgap=4.55 bottomlayer_prefgap=4.55 bottomlayer_minwidth=5.65 bottomlayer_maxwidth=5.65 bottomlayer_prefwidth=5.65 substack1={9319A519-0D26-40B3-8AF8-C4998BECF1C7} toplayer_{9319a519-0d26-40b3-8af8-c4998becf1c7}_mingap=10 toplayer_{9319a519-0d26-40b3-8af8-c4998becf1c7}_maxgap=10 toplayer_{9319a519-0d26-40b3-8af8-c4998becf1c7}_prefgap=10 toplayer_{9319a519-0d26-40b3-8af8-c4998becf1c7}_minwidth=15 toplayer_{9319a519-0d26-40b3-8af8-c4998becf1c7}_maxwidth=15 toplayer_{9319a519-0d26-40b3-8af8-c4998becf1c7}_prefwidth=15 midlayer2_{9319a519-0d26-40b3-8af8-c4998becf1c7}_mingap=10 midlayer2_{9319a519-0d26-40b3-8af8-c4998becf1c7}_maxgap=10 midlayer2_{9319a519-0d26-40b3-8af8-c4998becf1c7}_prefgap=10 midlayer2_{9319a519-0d26-40b3-8af8-c4998becf1c7}_minwidth=15 midlayer2_{9319a519-0d26-40b3-8af8-c4998becf1c7}_maxwidth=15 midlayer2_{9319a519-0d26-40b3-8af8-c4998becf1c7}_prefwidth=15 midlayer3_{9319a519-0d26-40b3-8af8-c4998becf1c7}_mingap=10 midlayer3_{9319a519-0d26-40b3-8af8-c4998becf1c7}_maxgap=10 midlayer3_{9319a519-0d26-40b3-8af8-c4998becf1c7}_prefgap=10 midlayer3_{9319a519-0d26-40b3-8af8-c4998becf1c7}_minwidth=15 midlayer3_{9319a519-0d26-40b3-8af8-c4998becf1c7}_maxwidth=15 midlayer3_{9319a519-0d26-40b3-8af8-c4998becf1c7}_prefwidth=15 midlayer5_{9319a519-0d26-40b3-8af8-c4998becf1c7}_mingap=10 midlayer5_{9319a519-0d26-40b3-8af8-c4998becf1c7}_maxgap=10 midlayer5_{9319a519-0d26-40b3-8af8-c4998becf1c7}_prefgap=10 midlayer5_{9319a519-0d26-40b3-8af8-c4998becf1c7}_minwidth=15 midlayer5_{9319a519-0d26-40b3-8af8-c4998becf1c7}_maxwidth=15 midlayer5_{9319a519-0d26-40b3-8af8-c4998becf1c7}_prefwidth=15 midlayer6_{9319a519-0d26-40b3-8af8-c4998becf1c7}_mingap=10 midlayer6_{9319a519-0d26-40b3-8af8-c4998becf1c7}_maxgap=10 midlayer6_{9319a519-0d26-40b3-8af8-c4998becf1c7}_prefgap=10 midlayer6_{9319a519-0d26-40b3-8af8-c4998becf1c7}_minwidth=15 midlayer6_{9319a519-0d26-40b3-8af8-c4998becf1c7}_maxwidth=15 midlayer6_{9319a519-0d26-40b3-8af8-c4998becf1c7}_prefwidth=15 midlayer7_{9319a519-0d26-40b3-8af8-c4998becf1c7}_mingap=10 midlayer7_{9319a519-0d26-40b3-8af8-c4998becf1c7}_maxgap=10 midlayer7_{9319a519-0d26-40b3-8af8-c4998becf1c7}_prefgap=10 midlayer7_{9319a519-0d26-40b3-8af8-c4998becf1c7}_minwidth=15 midlayer7_{9319a519-0d26-40b3-8af8-c4998becf1c7}_maxwidth=15 midlayer7_{9319a519-0d26-40b3-8af8-c4998becf1c7}_prefwidth=15 midlayer8_{9319a519-0d26-40b3-8af8-c4998becf1c7}_mingap=10 midlayer8_{9319a519-0d26-40b3-8af8-c4998becf1c7}_maxgap=10 midlayer8_{9319a519-0d26-40b3-8af8-c4998becf1c7}_prefgap=10 midlayer8_{9319a519-0d26-40b3-8af8-c4998becf1c7}_minwidth=15 midlayer8_{9319a519-0d26-40b3-8af8-c4998becf1c7}_maxwidth=15 midlayer8_{9319a519-0d26-40b3-8af8-c4998becf1c7}_prefwidth=15 bottomlayer_{9319a519-0d26-40b3-8af8-c4998becf1c7}_mingap=10 bottomlayer_{9319a519-0d26-40b3-8af8-c4998becf1c7}_maxgap=10 bottomlayer_{9319a519-0d26-40b3-8af8-c4998becf1c7}_prefgap=10 bottomlayer_{9319a519-0d26-40b3-8af8-c4998becf1c7}_minwidth=15 bottomlayer_{9319a519-0d26-40b3-8af8-c4998becf1c7}_maxwidth=15 bottomlayer_{9319a519-0d26-40b3-8af8-c4998becf1c7}_prefwidth=15 maxuncoupledlength=200
FabricationTestPointUsage TestPointUsage [All] p1: valid=2 allowmultiple=FALSE
FabricationTestpoint Testpoint [All] p1: side=3 testpointundercomponent=TRUE minsize=40 maxsize=100 preferedsize=60 minholesize=0 maxholesize=40 preferedholesize=32 testpointgrid=1 allowsidetop=TRUE allowsidebottom=TRUE usegrid=TRUE gridtolerance=0.01
FanoutControl Fanout_BGA [InComponent('U29')] p1: bgadir=Out bgaviamode=Centered fanoutstyle=Auto fanoutdirection=Alternating viagrid=1 // Fanout_BGA (Default Rule)
HoleSize [All] p1: absolutevalues=TRUE maxlimit=251 minlimit=5.9 maxpercent=80.000 minpercent=20.000
HoleToHoleClearance [All] p1: gap=5 allowstackedmicrovias=TRUE
MatchedLengths QSPI [InxSignalClass('QSPI')] p1: tolerance=12.5 checknetsindiffpair=FALSE checkdiffpairvsdiffpair=TRUE checkxsignals=TRUE checkothers=TRUE
MatchedLengths FTDI_SPI [InxSignalClass('FTDI_SPI')] p2: tolerance=50 checknetsindiffpair=FALSE checkdiffpairvsdiffpair=TRUE checkxsignals=TRUE checkothers=TRUE
MatchedLengths MSS_SPIB [InxSignalClass('MSS_SPIB')] p3: tolerance=50 checknetsindiffpair=FALSE checkdiffpairvsdiffpair=TRUE checkxsignals=TRUE checkothers=TRUE
MatchedLengths DBG_SPI [InxSignalClass('DBG_SPI')] p4: tolerance=50 checknetsindiffpair=FALSE checkdiffpairvsdiffpair=TRUE checkxsignals=TRUE checkothers=TRUE
MatchedLengths ETH_TX_U4 [InxSignalClass('ETH_TX_U4')] p5: tolerance=12.5 checknetsindiffpair=FALSE checkdiffpairvsdiffpair=TRUE checkxsignals=TRUE checkothers=TRUE
MatchedLengths ETH_TX_U15 [InxSignalClass('ETH_TX_U15')] p6: tolerance=12.5 checknetsindiffpair=FALSE checkdiffpairvsdiffpair=TRUE checkxsignals=TRUE checkothers=TRUE
MatchedLengths ETH_RX_U4 [InxSignalClass('ETH_RX_U4')] p7: tolerance=12.5 checknetsindiffpair=FALSE checkdiffpairvsdiffpair=TRUE checkxsignals=TRUE checkothers=TRUE
MatchedLengths ETH_RX_U15 [InxSignalClass('ETH_RX_U15')] p8: tolerance=12.5 checknetsindiffpair=FALSE checkdiffpairvsdiffpair=TRUE checkxsignals=TRUE checkothers=TRUE
MatchedLengths TRACE_Data [InxSignalClass('Trace')] p9: tolerance=50 checknetsindiffpair=FALSE checkdiffpairvsdiffpair=TRUE checkxsignals=TRUE checkothers=TRUE
MatchedLengths TD [InxSignalClass('TD')] p10: tolerance=12.5 checknetsindiffpair=FALSE checkdiffpairvsdiffpair=TRUE checkxsignals=TRUE checkothers=TRUE
MatchedLengths CSI_SET_1 [InxSignalClass('CSI_SET_1')] p11: tolerance=2 checknetsindiffpair=FALSE checkdiffpairvsdiffpair=TRUE checkxsignals=TRUE checkothers=TRUE
MatchedLengths CSI_SET_2 [InxSignalClass('CSI_SET_2')] p12: tolerance=10 checknetsindiffpair=FALSE checkdiffpairvsdiffpair=TRUE checkxsignals=TRUE checkothers=TRUE
MatchedLengths CSI_SET_1_DIFF [InxSignalClass('CSI_SET_1')] p13: tolerance=2 checknetsindiffpair=TRUE checkdiffpairvsdiffpair=FALSE checkxsignals=FALSE checkothers=FALSE
MatchedLengths CSI_SET_2_DIFF [InxSignalClass('CSI_SET_2')] p14: tolerance=2 checknetsindiffpair=TRUE checkdiffpairvsdiffpair=FALSE checkxsignals=FALSE checkothers=FALSE
MinimumAnnularRing MinimumAnnularRing_ThermalPadVias [IsVia and InAnyComponent] p1: minimumring=5
MinimumAnnularRing [All] p2 off: minimumring=6
MinimumSolderMaskSliver MinimumSolderMaskSliver_Logo [InComponentClass('Logo') vs InComponentClass('Logo')] p1: minsoldermaskwidth=0.7
MinimumSolderMaskSliver [All] p2: minsoldermaskwidth=3
PlaneConnect [All] p1: planeconnectstyle=Relief reliefexpansion=10 reliefentries=4 reliefconductorwidth=10 reliefairgap=10
PolygonConnect PolygonConnect_3 [All] p1: connectstyle=Direct reliefconductorwidth=10 reliefentries=4 polygonreliefangle="90 Angle" airgapwidth=10
PolygonConnect PolygonConnect_2 [All vs IsNamedPolygon('Top Layer-AGND 1')] p2: connectstyle=Direct reliefconductorwidth=10 reliefentries=4 polygonreliefangle="90 Angle" airgapwidth=10
PolygonConnect PolygonConnect_1 [All vs IsNamedPolygon('AGND_L06_P304')] p3: connectstyle=Direct reliefconductorwidth=10 reliefentries=4 polygonreliefangle="90 Angle" airgapwidth=10
PolygonConnect [All] p4: connectstyle=Direct reliefconductorwidth=10 reliefentries=4 polygonreliefangle="90 Angle" airgapwidth=10
RoomDefinition RouteCNTRL [False] p1: confinementstyle=ConfineIn formatcopy=TRUE lockcomponents=FALSE outline 2598.02,3662.51 2239.05,3662.51 2239.05,4124.13 2718.86,4124.13 2718.86,3662.14 2630.61,3662.14 2630.61,3554.13 2870,3554.13 2870,4300 2810.45,4359.55 2132.24,4359.55 2106.08,4333.39 2106.08,3343.92 2170,3280 2598.02,3280
RoomDefinition BGA [False] p2: confinementstyle=ConfineIn formatcopy=TRUE lockcomponents=FALSE outline 2238.73,3662.03 2238.73,4134.47 2727.51,4134.47 2727.51,3662.03
RoomDefinition U6_ [InComponent('U6')] p3: confinementstyle=ConfineIn formatcopy=TRUE lockcomponents=FALSE outline 1117,1155 1986,1155 1986,271 1117,271
RoomDefinition U8_ [InComponent('U8')] p4: confinementstyle=ConfineIn formatcopy=TRUE lockcomponents=FALSE outline 2226,2393 2584,2393 2584,2119 2226,2119
RoutingVias [All] p1: holewidth=8 width=18 viastyle="Through Hole" minholewidth=5.9 minwidth=13.77 maxholewidth=12 maxwidth=22 useviatemplates=TRUE viatemplateguid#1={4B97B95E-DC76-43D7-ABEE-7BD219FA4728} viatemplateguid#2={66879920-C408-450C-B1E7-018690666DE6} viatemplateguid#3={7578367A-1309-4EA2-B244-9BD0C24F2A2D} viatemplateguid#4={B731BD02-90A4-4180-B976-79033AA221F6} viatemplateguid#5={E7D83177-EB4F-48EB-A44C-AD515881CC95} viatemplateguid#6={863F6E68-6355-450A-A3E5-3FA68B4F68C1} viatemplatename#1=v41h20z46m0mx0(Tol8-8) viatemplatename#2=v46h20m0mx0 viatemplatename#3=v46h20m0mx0(Tol8-8) viatemplatename#4=v50h20 viatemplatename#5=v50h20m50 viatemplatename#6=v51h25m0mx0(Tol8-8)
SMDEntry [All] p1: side=TRUE corner=FALSE anyangle=TRUE
ShortCircuit Dog_Bone_BGA [IsBoardCutoutRegion] p1: allowed=TRUE
ShortCircuit [All] p2: allowed=FALSE
SilkToBoardRegionClearance [Not ((IsComment or IsDesignator) And (Hide <> 'False')) and not InRegion(1000,500,4000,800)] p1:
SilkToSilkClearance SilkToSilkClearance_Pb-FreeLogo [(HasFootprint('Pb-Free_Overlay_Medium') OR HasFootprint('Pb-Free_Overlay_Small')) vs (HasFootprint('Pb-Free_Overlay_Medium') OR HasFootprint('Pb-Free_Overlay_Small'))] p1: silktosilkclearance=0
SilkToSilkClearance [All] p2: silktosilkclearance=0
SilkToSolderMaskClearance SilkToComponentPadClearance [(IsPad or IsFill or IsRegion) and InAnycomponent] p1: minsilkscreentomaskgap=3 clearancetoexposedcopper=TRUE
SilkToSolderMaskClearance "Silk to Solder Mask Opening" [All] p2: minsilkscreentomaskgap=3 clearancetoexposedcopper=FALSE
SolderMaskExpansion [All] p1: expansion=1.97 istentingtop=FALSE
UnRoutedNet [All] p1: checkbadconnections=TRUE
Width "Diff Pair" [InAnyDifferentialPair] p1: maxlimit=50 minlimit=4.8 preferedwidth=10 substack1={9319A519-0D26-40B3-8AF8-C4998BECF1C7} toplayer_{9319a519-0d26-40b3-8af8-c4998becf1c7}_minwidth=10 toplayer_{9319a519-0d26-40b3-8af8-c4998becf1c7}_maxwidth=10 midlayer2_{9319a519-0d26-40b3-8af8-c4998becf1c7}_minwidth=10 midlayer2_{9319a519-0d26-40b3-8af8-c4998becf1c7}_maxwidth=10 midlayer3_{9319a519-0d26-40b3-8af8-c4998becf1c7}_minwidth=10 midlayer3_{9319a519-0d26-40b3-8af8-c4998becf1c7}_maxwidth=10 midlayer5_{9319a519-0d26-40b3-8af8-c4998becf1c7}_minwidth=10 midlayer5_{9319a519-0d26-40b3-8af8-c4998becf1c7}_maxwidth=10 midlayer6_{9319a519-0d26-40b3-8af8-c4998becf1c7}_minwidth=10 midlayer6_{9319a519-0d26-40b3-8af8-c4998becf1c7}_maxwidth=10 midlayer7_{9319a519-0d26-40b3-8af8-c4998becf1c7}_minwidth=10 midlayer7_{9319a519-0d26-40b3-8af8-c4998becf1c7}_maxwidth=10 midlayer8_{9319a519-0d26-40b3-8af8-c4998becf1c7}_minwidth=10 midlayer8_{9319a519-0d26-40b3-8af8-c4998becf1c7}_maxwidth=10 bottomlayer_{9319a519-0d26-40b3-8af8-c4998becf1c7}_minwidth=10 bottomlayer_{9319a519-0d26-40b3-8af8-c4998becf1c7}_maxwidth=10
Width Width_RouteCTRL [WithinRoom('RouteCNTRL')] p2: maxlimit=50 minlimit=4 preferedwidth=6 midlayer2_minwidth=6 midlayer3_minwidth=6 midlayer5_minwidth=6 midlayer6_minwidth=6 midlayer7_minwidth=6 midlayer8_minwidth=6 bottomlayer_prefwidth=8 substack1={9319A519-0D26-40B3-8AF8-C4998BECF1C7} toplayer_{9319a519-0d26-40b3-8af8-c4998becf1c7}_minwidth=6 toplayer_{9319a519-0d26-40b3-8af8-c4998becf1c7}_maxwidth=10 toplayer_{9319a519-0d26-40b3-8af8-c4998becf1c7}_prefwidth=10 midlayer2_{9319a519-0d26-40b3-8af8-c4998becf1c7}_minwidth=6 midlayer2_{9319a519-0d26-40b3-8af8-c4998becf1c7}_maxwidth=10 midlayer2_{9319a519-0d26-40b3-8af8-c4998becf1c7}_prefwidth=10 midlayer3_{9319a519-0d26-40b3-8af8-c4998becf1c7}_minwidth=6 midlayer3_{9319a519-0d26-40b3-8af8-c4998becf1c7}_maxwidth=10 midlayer3_{9319a519-0d26-40b3-8af8-c4998becf1c7}_prefwidth=10 midlayer5_{9319a519-0d26-40b3-8af8-c4998becf1c7}_minwidth=6 midlayer5_{9319a519-0d26-40b3-8af8-c4998becf1c7}_maxwidth=10 midlayer5_{9319a519-0d26-40b3-8af8-c4998becf1c7}_prefwidth=10 midlayer6_{9319a519-0d26-40b3-8af8-c4998becf1c7}_minwidth=6 midlayer6_{9319a519-0d26-40b3-8af8-c4998becf1c7}_maxwidth=10 midlayer6_{9319a519-0d26-40b3-8af8-c4998becf1c7}_prefwidth=10 midlayer7_{9319a519-0d26-40b3-8af8-c4998becf1c7}_minwidth=6 midlayer7_{9319a519-0d26-40b3-8af8-c4998becf1c7}_maxwidth=10 midlayer7_{9319a519-0d26-40b3-8af8-c4998becf1c7}_prefwidth=10 midlayer8_{9319a519-0d26-40b3-8af8-c4998becf1c7}_minwidth=6 midlayer8_{9319a519-0d26-40b3-8af8-c4998becf1c7}_maxwidth=10 midlayer8_{9319a519-0d26-40b3-8af8-c4998becf1c7}_prefwidth=10 bottomlayer_{9319a519-0d26-40b3-8af8-c4998becf1c7}_minwidth=6 bottomlayer_{9319a519-0d26-40b3-8af8-c4998becf1c7}_maxwidth=10 bottomlayer_{9319a519-0d26-40b3-8af8-c4998becf1c7}_prefwidth=10 minimp=50.000000 maximp=50.000000 favimp=50.000000
Width Width_BGA [WithinRoom('BGA')] p3: maxlimit=50 minlimit=4 preferedwidth=6 toplayer_prefwidth=4 midlayer2_minwidth=6 midlayer3_minwidth=6 midlayer5_minwidth=6 midlayer6_minwidth=6 midlayer7_minwidth=6 midlayer8_minwidth=6 bottomlayer_prefwidth=4 substack1={9319A519-0D26-40B3-8AF8-C4998BECF1C7} toplayer_{9319a519-0d26-40b3-8af8-c4998becf1c7}_minwidth=4.19 toplayer_{9319a519-0d26-40b3-8af8-c4998becf1c7}_maxwidth=4.19 toplayer_{9319a519-0d26-40b3-8af8-c4998becf1c7}_prefwidth=4.19 midlayer2_{9319a519-0d26-40b3-8af8-c4998becf1c7}_minwidth=4.19 midlayer2_{9319a519-0d26-40b3-8af8-c4998becf1c7}_maxwidth=4.19 midlayer2_{9319a519-0d26-40b3-8af8-c4998becf1c7}_prefwidth=4.19 midlayer3_{9319a519-0d26-40b3-8af8-c4998becf1c7}_minwidth=4.19 midlayer3_{9319a519-0d26-40b3-8af8-c4998becf1c7}_maxwidth=4.19 midlayer3_{9319a519-0d26-40b3-8af8-c4998becf1c7}_prefwidth=4.19 midlayer5_{9319a519-0d26-40b3-8af8-c4998becf1c7}_minwidth=4.19 midlayer5_{9319a519-0d26-40b3-8af8-c4998becf1c7}_maxwidth=4.19 midlayer5_{9319a519-0d26-40b3-8af8-c4998becf1c7}_prefwidth=4.19 midlayer6_{9319a519-0d26-40b3-8af8-c4998becf1c7}_minwidth=4.19 midlayer6_{9319a519-0d26-40b3-8af8-c4998becf1c7}_maxwidth=4.19 midlayer6_{9319a519-0d26-40b3-8af8-c4998becf1c7}_prefwidth=4.19 midlayer7_{9319a519-0d26-40b3-8af8-c4998becf1c7}_minwidth=4.19 midlayer7_{9319a519-0d26-40b3-8af8-c4998becf1c7}_maxwidth=4.19 midlayer7_{9319a519-0d26-40b3-8af8-c4998becf1c7}_prefwidth=4.19 midlayer8_{9319a519-0d26-40b3-8af8-c4998becf1c7}_minwidth=4.19 midlayer8_{9319a519-0d26-40b3-8af8-c4998becf1c7}_maxwidth=4.19 midlayer8_{9319a519-0d26-40b3-8af8-c4998becf1c7}_prefwidth=4.19 bottomlayer_{9319a519-0d26-40b3-8af8-c4998becf1c7}_minwidth=4.19 bottomlayer_{9319a519-0d26-40b3-8af8-c4998becf1c7}_maxwidth=4.19 bottomlayer_{9319a519-0d26-40b3-8af8-c4998becf1c7}_prefwidth=4.19 minimp=50.000000 maximp=50.000000 favimp=50.000000
Width POWER [InNetClass('PWR')] p4: maxlimit=100 minlimit=1 preferedwidth=10 toplayer_maxwidth=50 midlayer2_minwidth=4 midlayer3_minwidth=4 midlayer5_minwidth=4 midlayer6_minwidth=4 midlayer7_minwidth=4 midlayer8_minwidth=4 bottomlayer_minwidth=7 bottomlayer_maxwidth=50 substack1={9319A519-0D26-40B3-8AF8-C4998BECF1C7} minimp=50.000000 maximp=50.000000 favimp=50.000000 checkconnectedcopper=TRUE
Width [All] p5: maxlimit=100 minlimit=4 preferedwidth=10 toplayer_minwidth=7 toplayer_maxwidth=30 toplayer_prefwidth=8 midlayer2_minwidth=10 midlayer3_minwidth=10 midlayer5_minwidth=10 midlayer6_minwidth=6 midlayer6_maxwidth=6 midlayer6_prefwidth=6 midlayer7_minwidth=6 midlayer7_maxwidth=6 midlayer7_prefwidth=6 midlayer8_minwidth=10 bottomlayer_maxwidth=30 bottomlayer_prefwidth=8 substack1={9319A519-0D26-40B3-8AF8-C4998BECF1C7} minimp=50.000000 maximp=50.000000 favimp=50.000000 checkconnectedcopper=TRUE
15 further rules are at their usual default settings.

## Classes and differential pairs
differential pair class DIFF_100E: CSI2_TX0_LVDS_TX0 CSI2_TX1_LVDS_TX1 CSI2_TX2_CLK_LVDS_FRCLK CSI2_TX3 CSI2_TX4_LVDS_CLK ETH_TD_1 ETH_TD_2 ETH_TD_3 ETH_TD_4 ETH_TRD FRCLK TRD1 TRD2 TRD3 TX0 TX1 TX2_CLK TX3 TX4
differential pair class DIFF_90E: FTDI_USBD XDSET_1_D
component class PROC158A_Auto_Ethernet_conn: C155 C156 C157 C161 C162 C166 C167 D15 D16 D17 D18 D19 J4 L7 L11 R191 R260 R265 R270 R274 R275 R281 R282
net class RESET: AR_NRST AR_WRMRST
net class GPIO: GPIO_3/XREF_CLK1 GPIO_4/XREF_CLK0 GPIO_8 GPIO_9 GPIO_30 GPIO_31 MSS_GPIO_0 MSS_GPIO_1 MSS_GPIO_2 MSS_GPIO_11 VPP_EN
net class 40MHz_CLK: CLKP_SMA GND NC_50MHz XO_50MHz XTALM XTALP
net class MSS_SPIB: MSS_SPIB_CLK MSS_SPIB_CS0 MSS_SPIB_CS1 MSS_SPIB_MISO MSS_SPIB_MOSI SOP1_MSS_SPIB_CS2
net class USB_DIFF: FTDI_USBD_N FTDI_USBD_P XDSET_1_D_N XDSET_1_D_P
component class PROC158A_3V3_Supply_Reference: C10 C21 C22 C23 C25 C26 C29 C118 C173 C195 L6 R1 R2 R4 R7 R8 R9 R10 U2
net class RGMII_TX_RX: MSS_RGMII_RCLK MSS_RGMII_RCTL MSS_RGMII_RD0 MSS_RGMII_RD1 MSS_RGMII_RD2 MSS_RGMII_RD3 MSS_RGMII_TCLK MSS_RGMII_TCTL MSS_RGMII_TD0 MSS_RGMII_TD1 MSS_RGMII_TD2 MSS_RGMII_TD3 RGMII_RD0 RGMII_RD1 RGMII_RD2 RGMII_RD3 RGMII_TCLK RGMII_TD0 RGMII_TD1 RGMII_TD2 RGMII_TD3 RX_CLK RX_CTRL TX_CTRL
component class PROC158A_VPP_LDO: C145 C149 P1 R159 R409 U27
net class UART: BSS_UARTA_TX MSS_RS232RX MSS_RS232TX MSS_UARTA_RX SOP3_MSS_UARTB_TX SOP4_MSS_UARTA_TX
net class PWR: 1V0_ETH 1V0_FILTERED 1V2_FILTERED 1V8_FILTERED 2V5_ETH 3V3_VIO ERTH_GND FTDI_3V3 FTDI_VBUS FTDI_VCORE GND MIPI_VREF_DEBUG NetC1_2 NetC34_2 NetC97_1 NetC104_1 NetC149_2 NetJ8_1 NetJ8_5 NetJ9_1 NetJ9_2 NetJ10_1 VBAT_INT VDDC_1 VDDIO_ETH VLDO_3V3 VPP_1P7 XDSET_1_VBUS XDSET_VBAT XDSET_VREFA
net class MDIO: MSS_MDIO_CLK MSS_MDIO_DATA
net class I2C: MSS_I2CA_SCL MSS_I2CA_SDA
net class XDS_USB: XDSET_1_D_N XDSET_1_D_P XDSET_1_ID
net class TRACE: MIPI_DBG_DETECT
net class RGMII: ETH2_RX_CLK ETH2_RX_CTRL ETH_TRD_N ETH_TRD_P MSS_MDIO_CLK MSS_MDIO_DATA MSS_RGMII_RCLK MSS_RGMII_RCTL MSS_RGMII_RD0 MSS_RGMII_RD1 MSS_RGMII_RD2 MSS_RGMII_RD3 MSS_RGMII_TCLK MSS_RGMII_TCTL MSS_RGMII_TD0 MSS_RGMII_TD1 MSS_RGMII_TD2 MSS_RGMII_TD3 NetR74_2 NetR96_2 NetR100_2 NetR178_2 NetR225_2 NetR230_2 NetR247_2 NetR249_2 RGMII_RD0 RGMII_RD1 RGMII_RD2 RGMII_RD3 RGMII_TCLK RGMII_TD0 RGMII_TD1 RGMII_TD2 RGMII_TD3 RX_CLK RX_CTRL RX_D0 RX_D1 RX_D2 RX_D3 TD_1_N TD_1_P TD_2_N TD_2_P TD_3_N TD_3_P TD_4_N TD_4_P TX_CTRL
net class QSPI: QSPI_CS QSPI_D0 QSPI_D0_FLASH QSPI_D1 QSPI_D1_FLASH QSPI_D2 QSPI_D2_FLASH QSPI_D3 QSPI_D3_FLASH QSPI_SCLK QSPI_SCLK_FLASH
net class CSI: CSI2_TX0_LVDS_TX0_N CSI2_TX0_LVDS_TX0_P CSI2_TX1_LVDS_TX1_N CSI2_TX1_LVDS_TX1_P CSI2_TX2_CLK_LVDS_FRCLK_N CSI2_TX2_CLK_LVDS_FRCLK_P CSI2_TX3_N CSI2_TX3_P CSI2_TX4_LVDS_CLK_N CSI2_TX4_LVDS_CLK_P FRCLK_N FRCLK_P TX0_N TX0_P TX1_N TX1_P TX2_CLK_N TX2_CLK_P TX3_N TX3_P TX4_N TX4_P
net class JTAG: DBG_SPI_CLK DBG_SPI_CS0 DBG_SPI_MISO DBG_SPI_MOSI EMU_TCK EMU_TDI EMU_TDO EMU_TMS FTDI_SPI_CLK FTDI_SPI_CS0 FTDI_SPI_MISO FTDI_SPI_MOSI MIPI_RTCK MSS_SPIB_CLK MSS_SPIB_CS0 MSS_SPIB_MISO MSS_SPIB_MOSI NetR188_1 NetR223_1 NetR353_2 NetR354_2 NetR355_2 NetR356_2 NetR357_2 NetR358_2 NetR359_2 NetR360_2 NetR377_2 NetR386_2 NetR399_1 SOP0_TDO TCK TDI TMS XDS_TCK XDS_TDI XDS_TDO XDS_TMS
net class GPADC: DBG_GPADC1 DBG_GPADC2 DBG_GPADC5 DBG_GPADC6 GND GPADC1 GPADC2 GPADC5 GPADC6
net class FTDI_USB: FTDI_USBD_N FTDI_USBD_P FTDI_USBID
net class CLKOUT: AR_SYNCIN DBG_EPWMA0 DBG_SPI_MISO DBG_XREF_CLK0 DBG_XREF_CLK1 MSS_EPWMA0 MSS_SPIA_HOSTIRQ NetJ7_10 NetJ7_16 XREF_CLK0 XREF_CLK1
component class "PROC158A_XDS110 Interface_1B": C49 C63 C66 C67 C70 C71 C109 R123 R124 R126 R127 R128 R129 R134 R136 R140 R152 R154 R155 R194 R284 R285 R387 R388 R389 U6 U7 Y2
component class "PROC158A_XDS110 Interface_1A": C41 C42 C43 C45 C50 C61 C62 C64 C74 C75 C76 J8 R161 R174 R175 U10
component class PROC158A_IO_Reference: C47 C106 C108 C131 C135 C136 C178 J2 J13 J14 J21 J22 J23 R3 R17 R18 R19 R21 R22 R23 R24 R25 R28 R31 R55 R83 R85 R86 R87 R95 R104 R133 R156 R165 R172 R189 R190 R216 R217 R218 R219 R220 R221 R224 R227 R228 R229 R231 R232 R233 R235 R236 R269 R271 R272 R273 R276 R277 R278 R279 R280 R315 R316 R326 R380 R381 R386 R416 R417 TP1 TP4 TP7 TP9 U28 U29 Y3 Y7
component class PROC158A_Decoupling_Reference: C5 C55 C92 C96 C102 C103 C107 C110 C111 C112 C113 C114 C115 C116 C117 C137 C138 C139 C140 C141 C142 C146 C150 C163 C164 C165 C168 C170 C174 C175 C176 C177 C180 C181
component class PROC158A_Temp_Sensor: C133 R222 R317 R318 R319 U24
component class PROC158A_SOP_Reference: J17 J18 J20 R298 R299 R300 R301 R302 R303 R304 R305 R306 R307 R308 R309 R310 R311 R312 R313
component class PROC158A_QSPI_Flash_Reference: C1 C2 R37 R38 R39 R40 R41 R42 R43 R44 R45 R49 U1
component class PROC158A_PWR_RST_LED: C99 C100 C101 C104 C105 C126 D2 D3 D4 D5 D6 D9 D11 D12 D13 DS2 J12 L5 Q1 R36 R261 R262 R263 R264 R266 R267 R268 R331 R333 R334 R335 R347 R362 SW1 SW2
component class PROC158A_PMIC_Reference: C3 C4 C6 C7 C9 C15 C31 C51 C58 C80 C119 C120 C122 C123 C124 C125 C127 C128 C129 C130 C132 C134 C143 C144 C147 C148 C151 C152 C153 C154 C169 C171 C182 C194 C198 C199 C200 J1 J3 J5 L1 L2 L8 L9 L12 NT1 NT2 NT3 NT4 R14 R20 R48 R52 R53 R54 R67 R70 R71 R99 R102 R106 R107 R109 R110 R111 R116 R125 R192 R193 R199 R200 R291 U8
